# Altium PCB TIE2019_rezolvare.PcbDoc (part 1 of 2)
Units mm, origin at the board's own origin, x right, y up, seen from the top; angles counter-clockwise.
Board outline 267 x 129 mm, 8 copper layers (Signal 1, GND/Signal 2, GND 3, Signal 4, GND, Power/Signal 6, GND 7, Signal 8), stack 1.597 mm thick; 97 components, 82 nets, 657 pads, 352 vias.
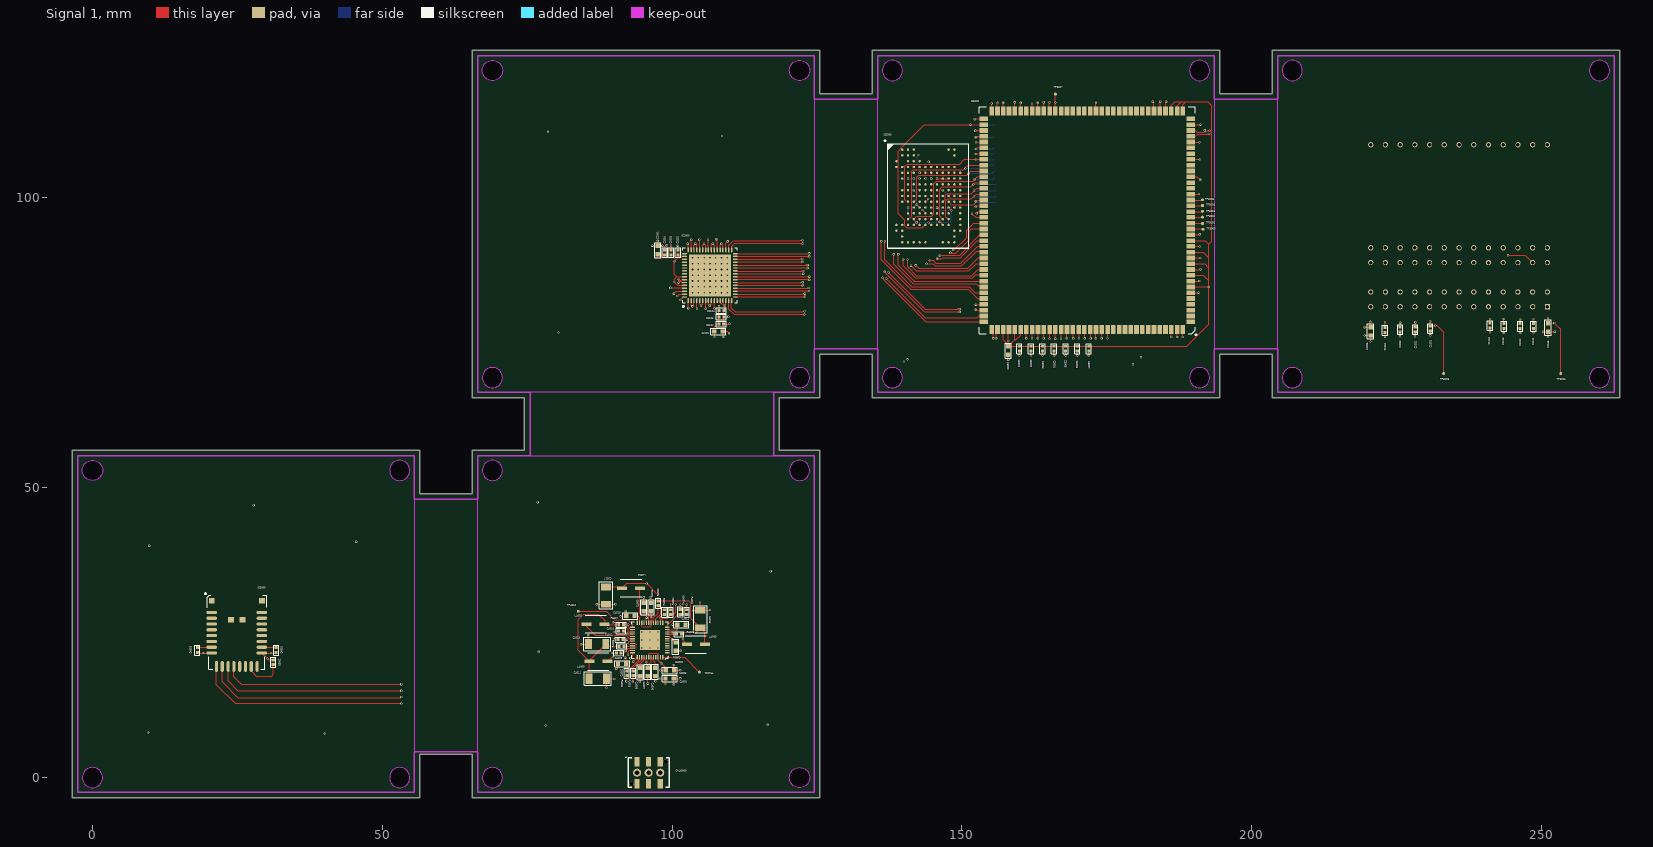
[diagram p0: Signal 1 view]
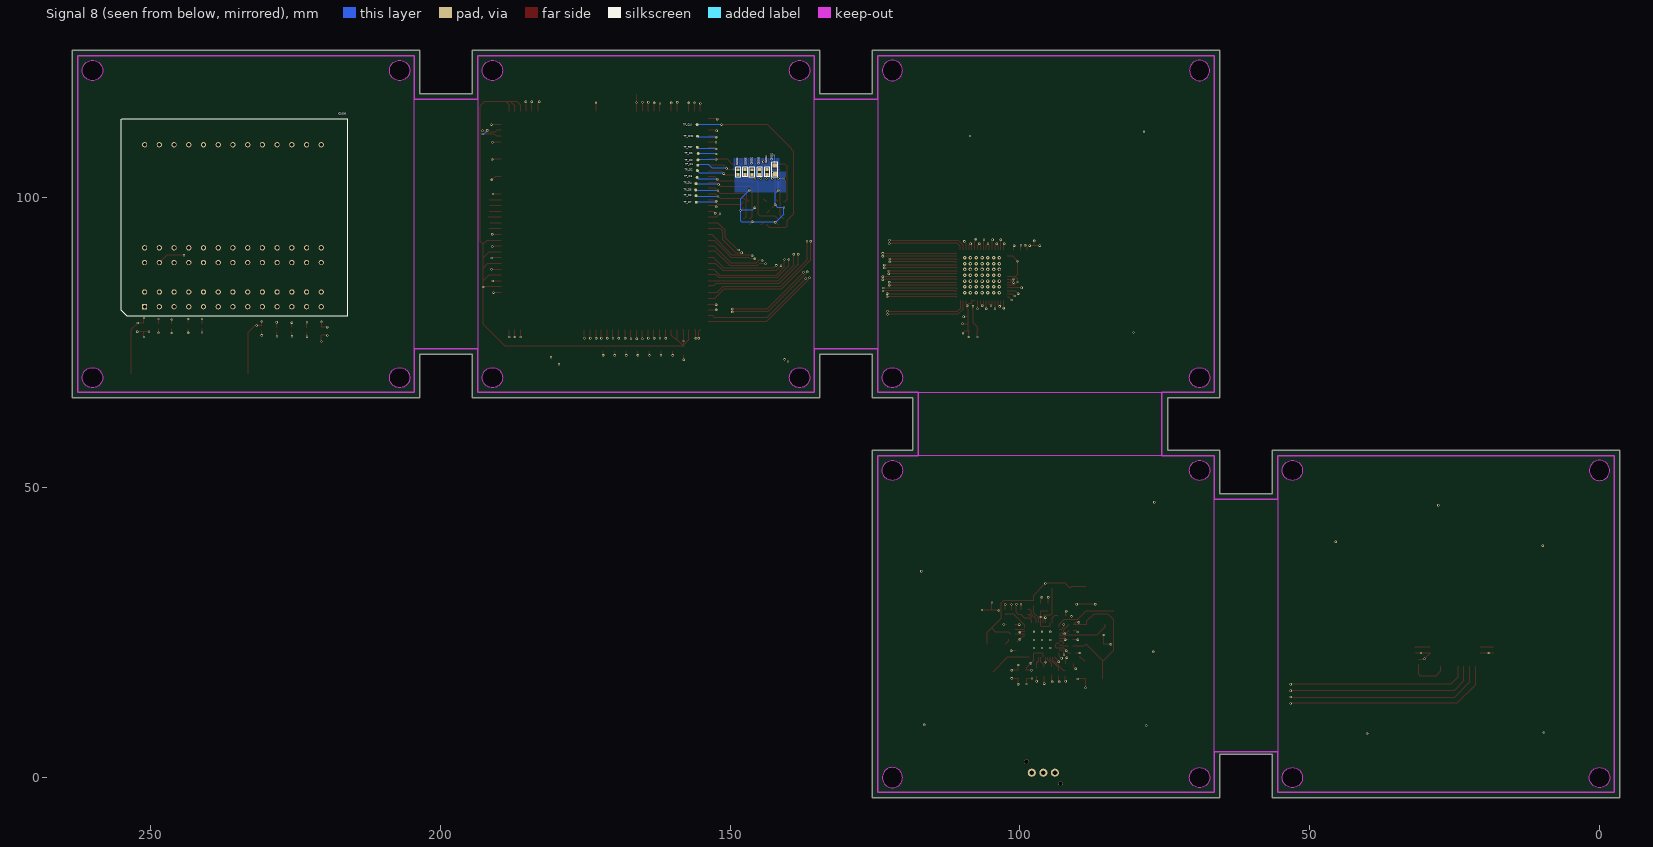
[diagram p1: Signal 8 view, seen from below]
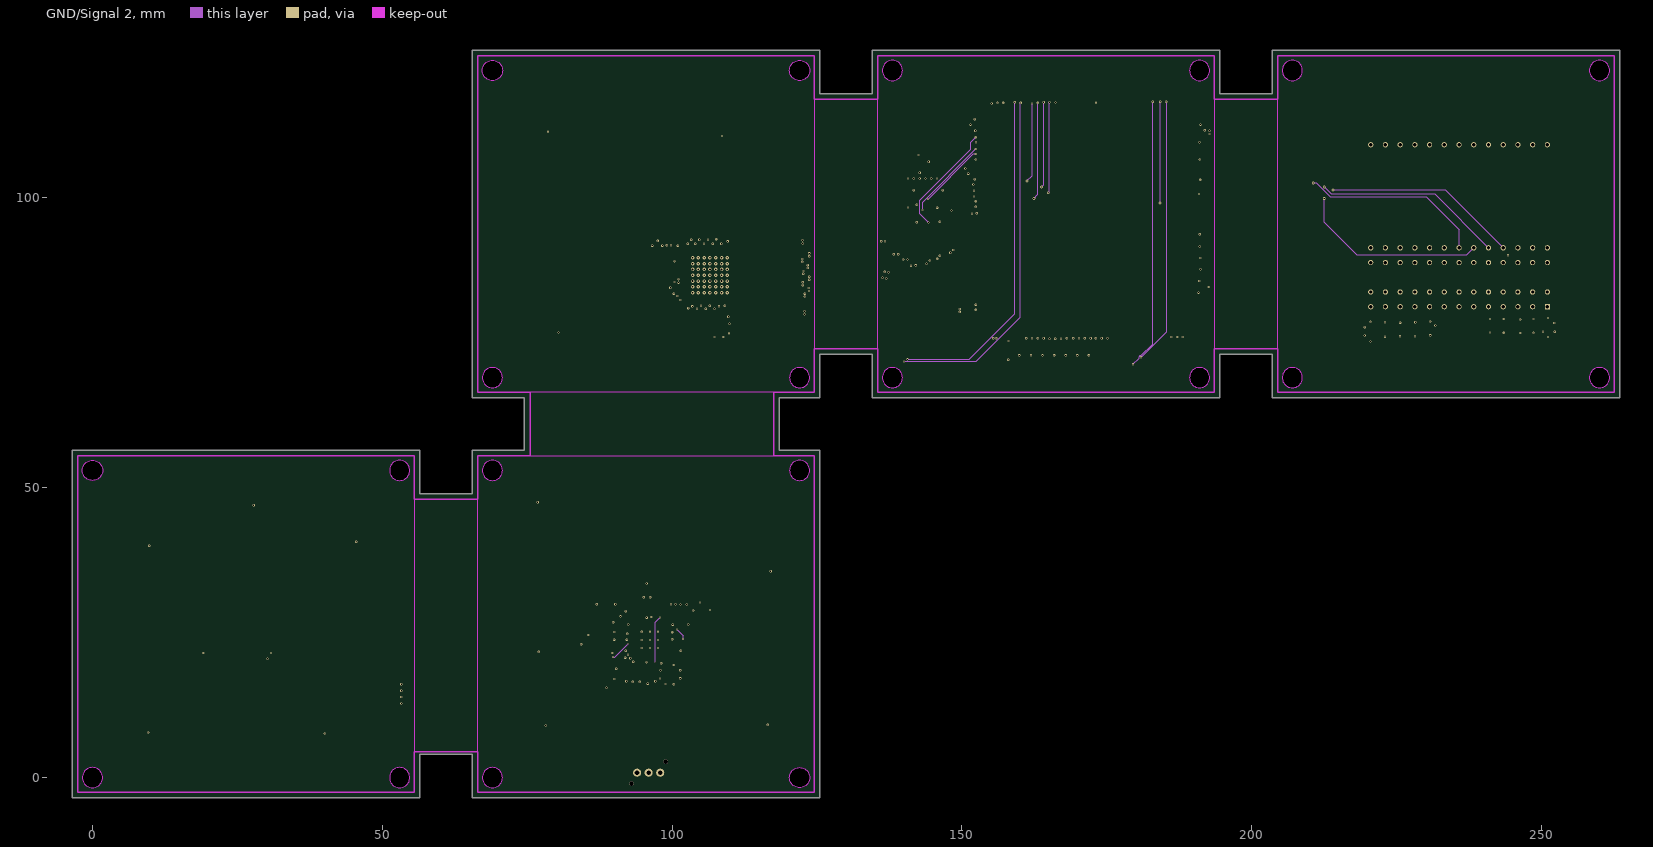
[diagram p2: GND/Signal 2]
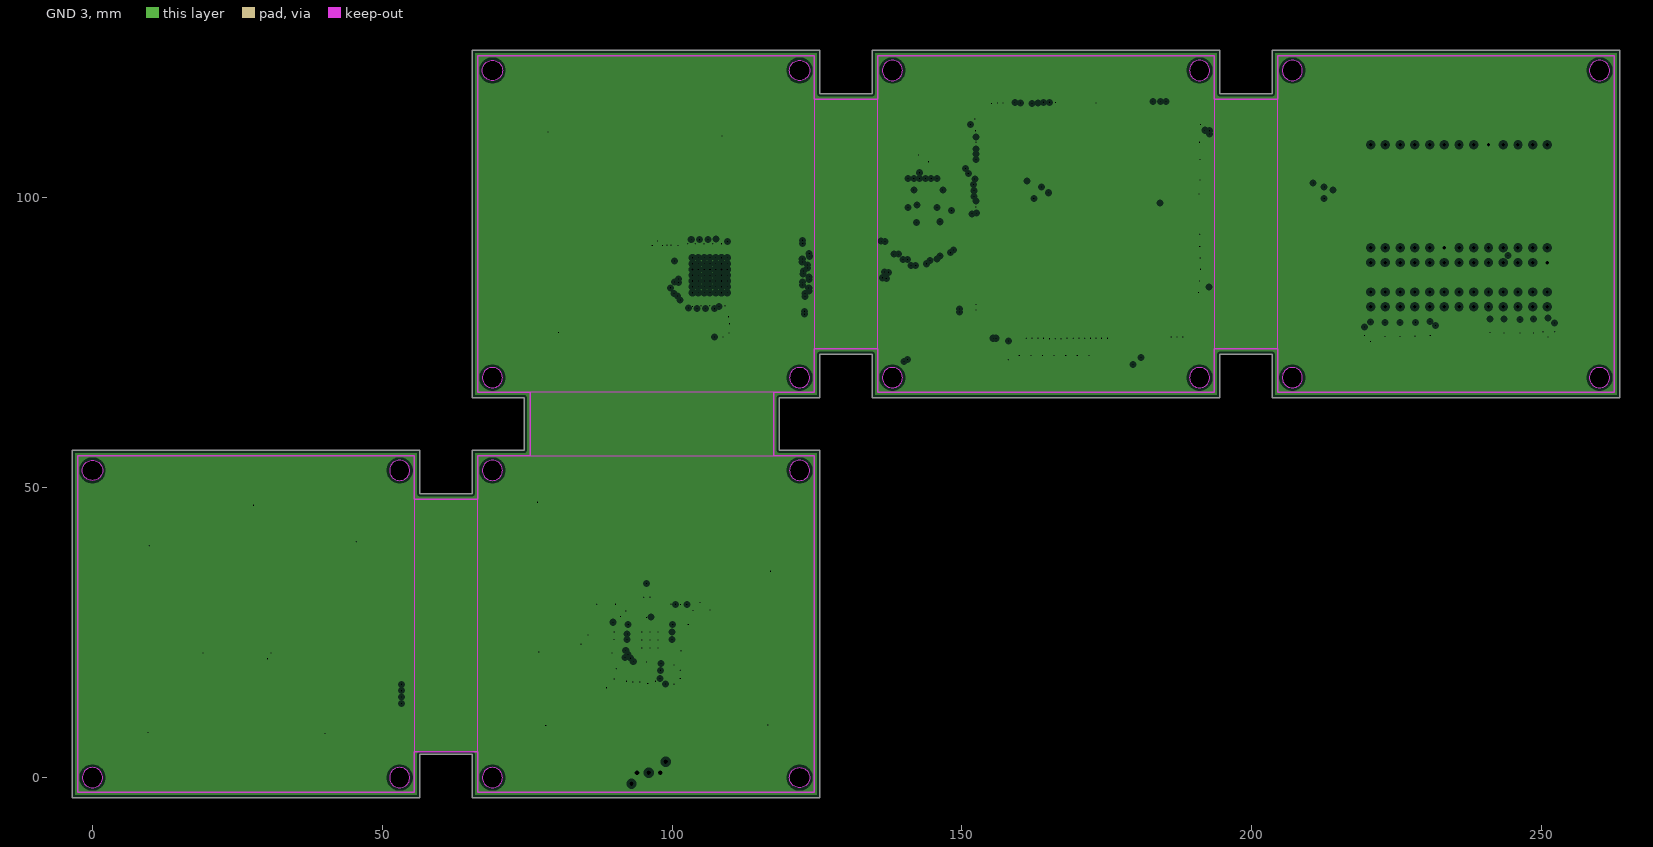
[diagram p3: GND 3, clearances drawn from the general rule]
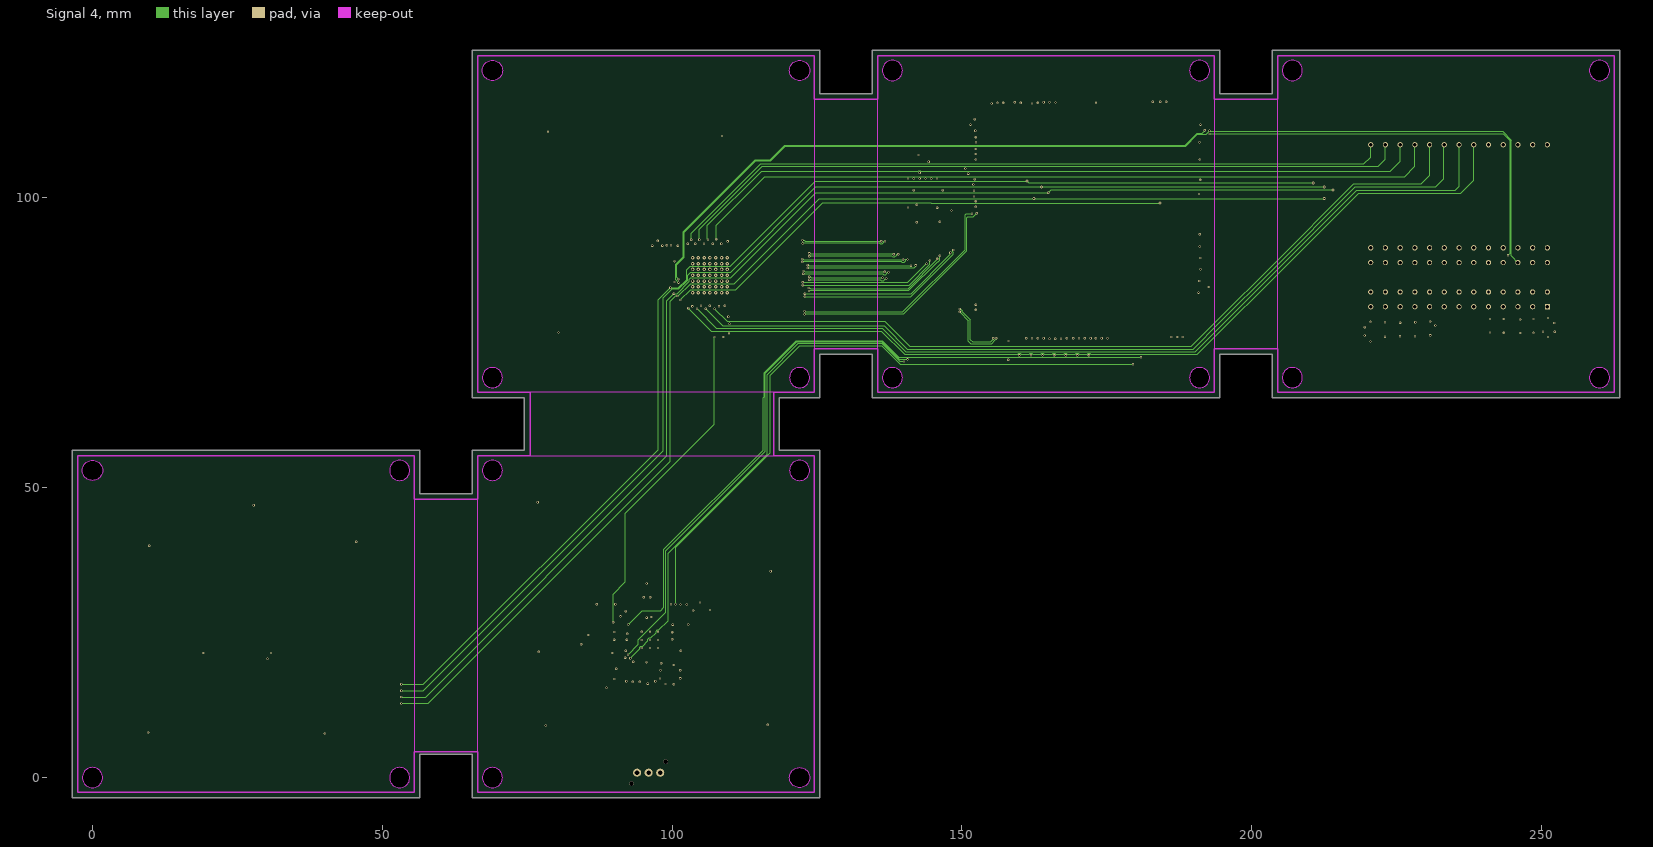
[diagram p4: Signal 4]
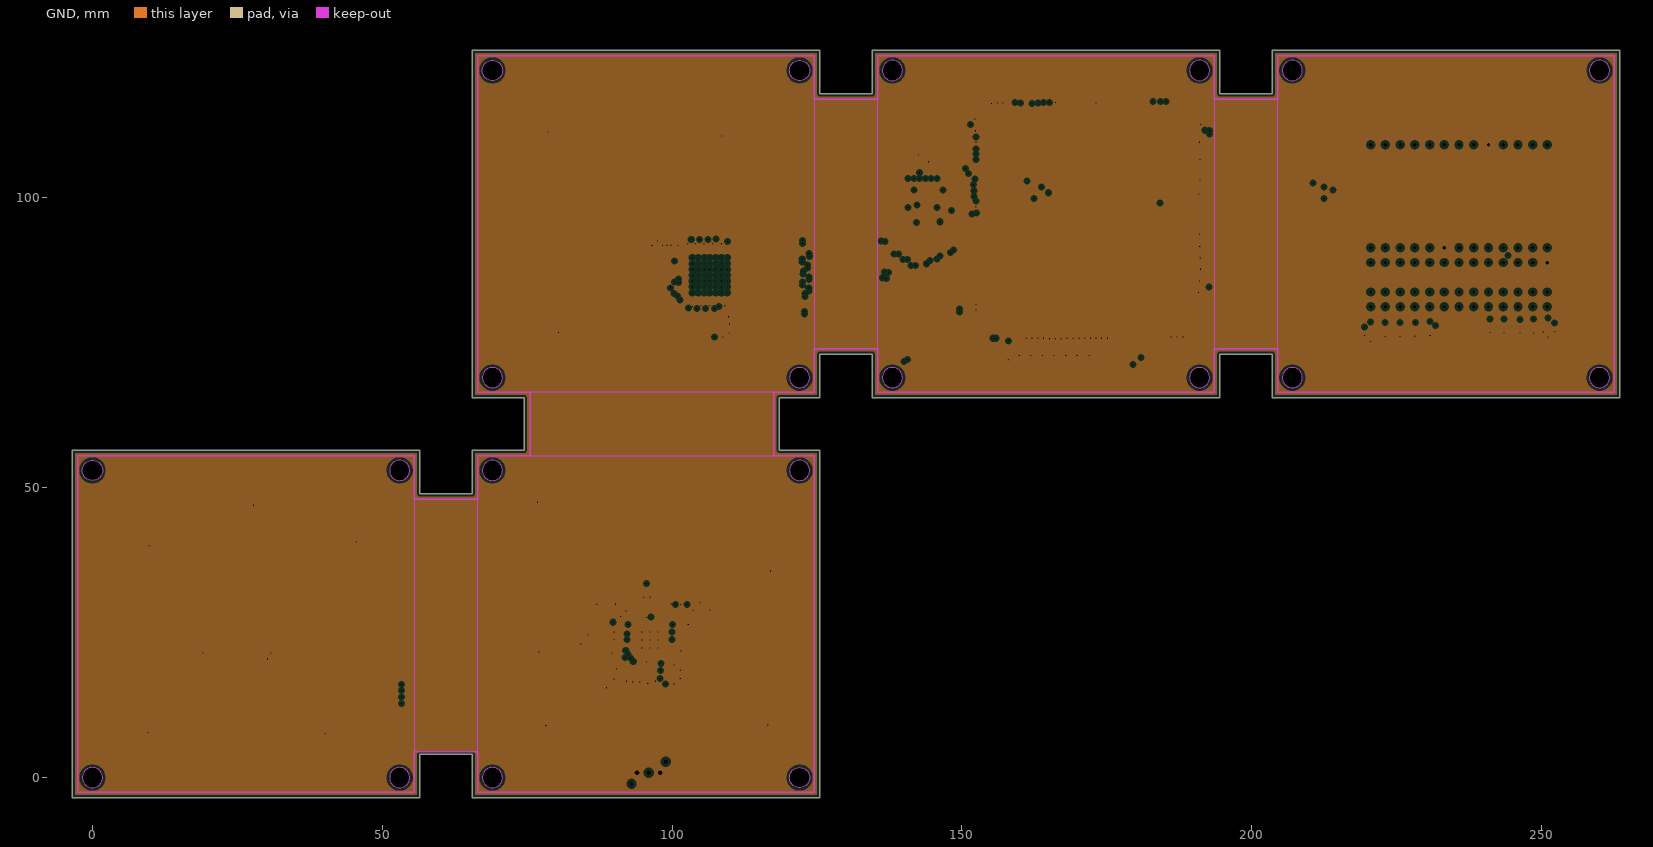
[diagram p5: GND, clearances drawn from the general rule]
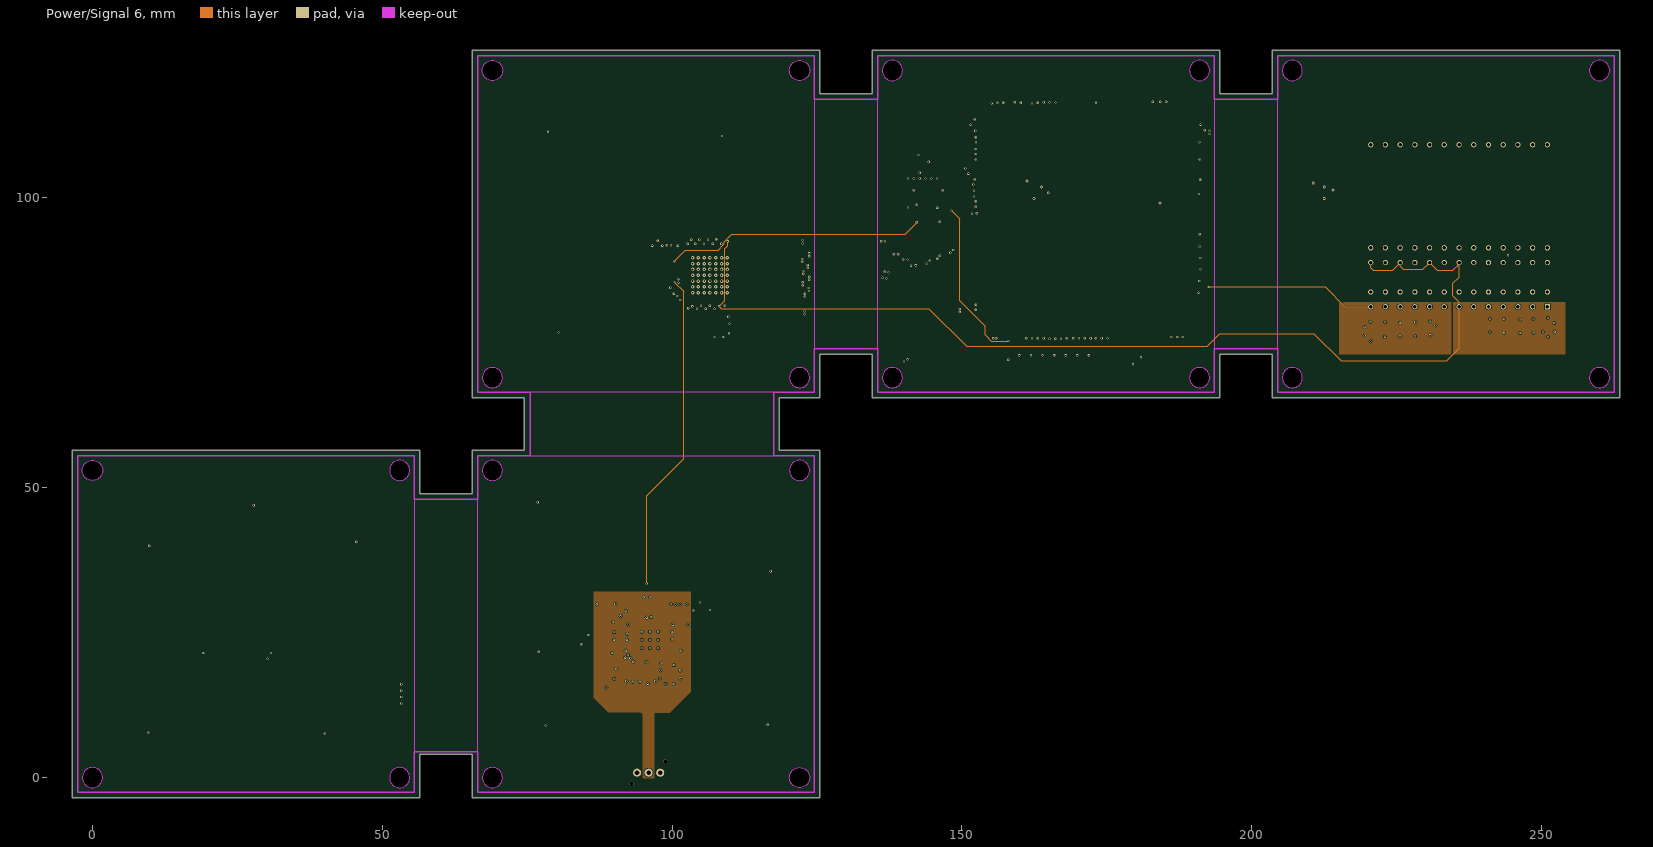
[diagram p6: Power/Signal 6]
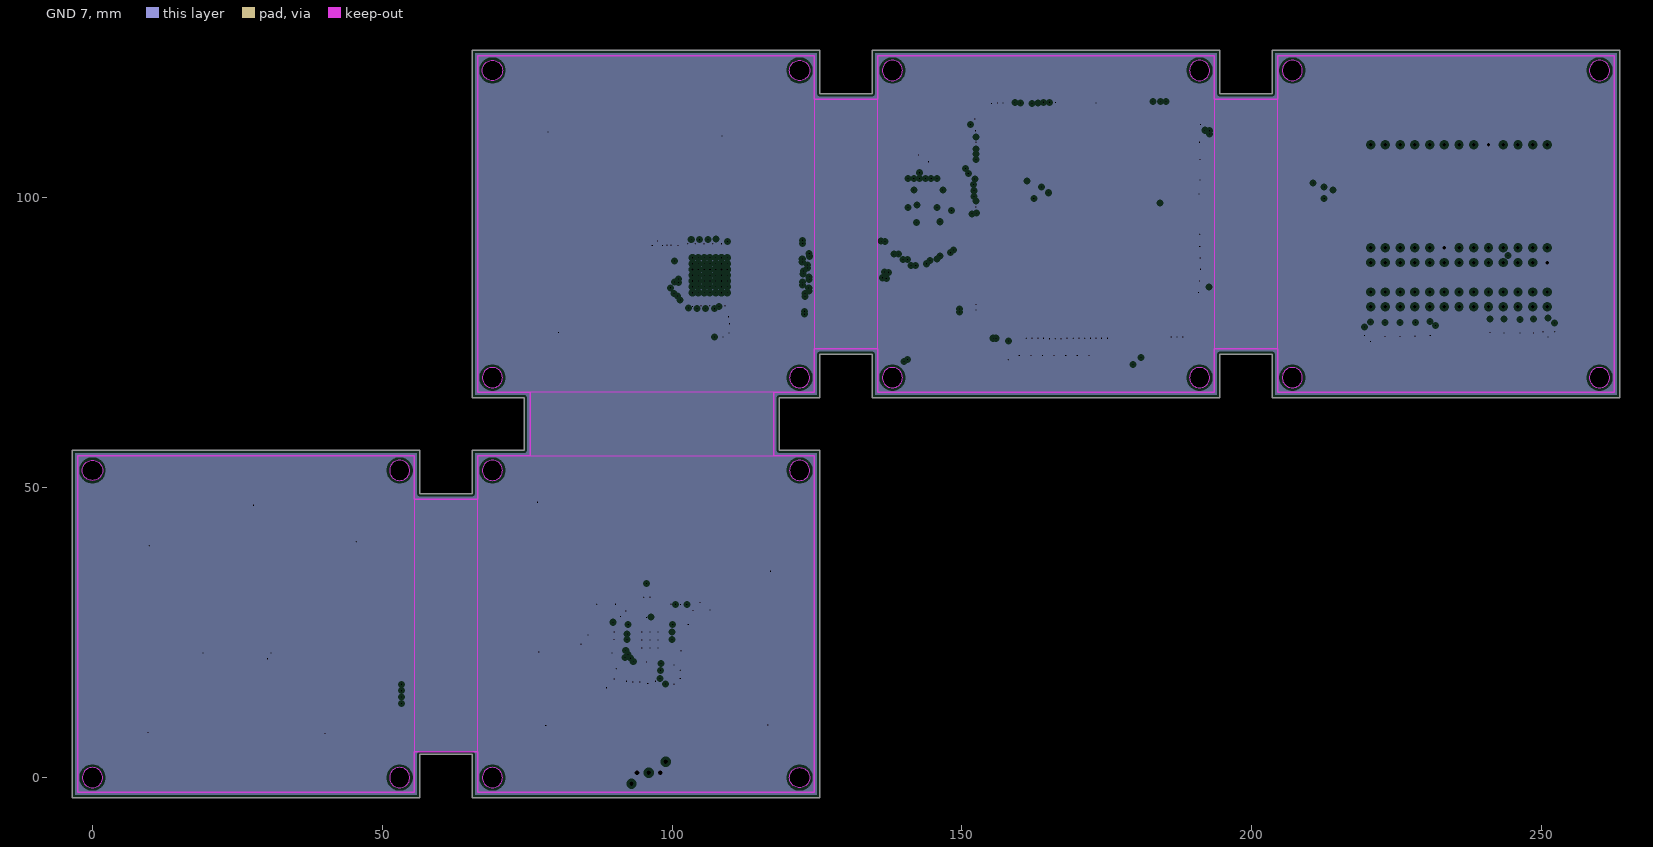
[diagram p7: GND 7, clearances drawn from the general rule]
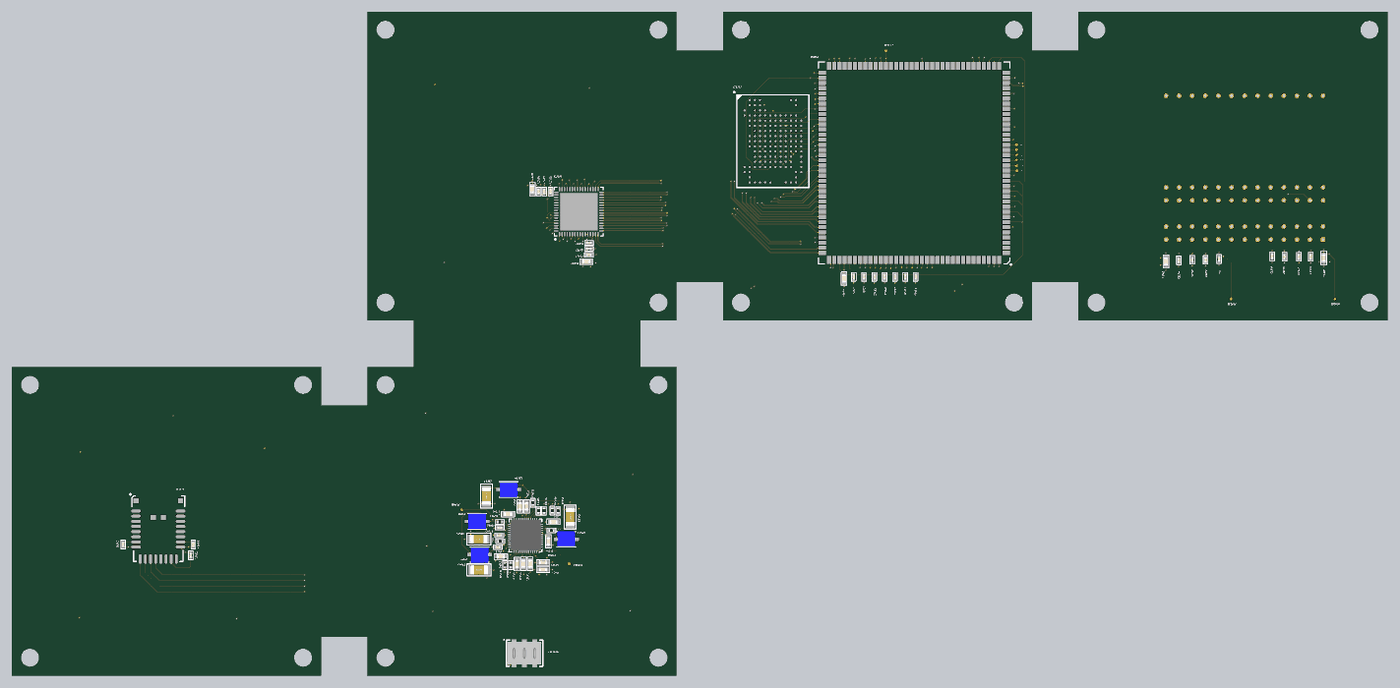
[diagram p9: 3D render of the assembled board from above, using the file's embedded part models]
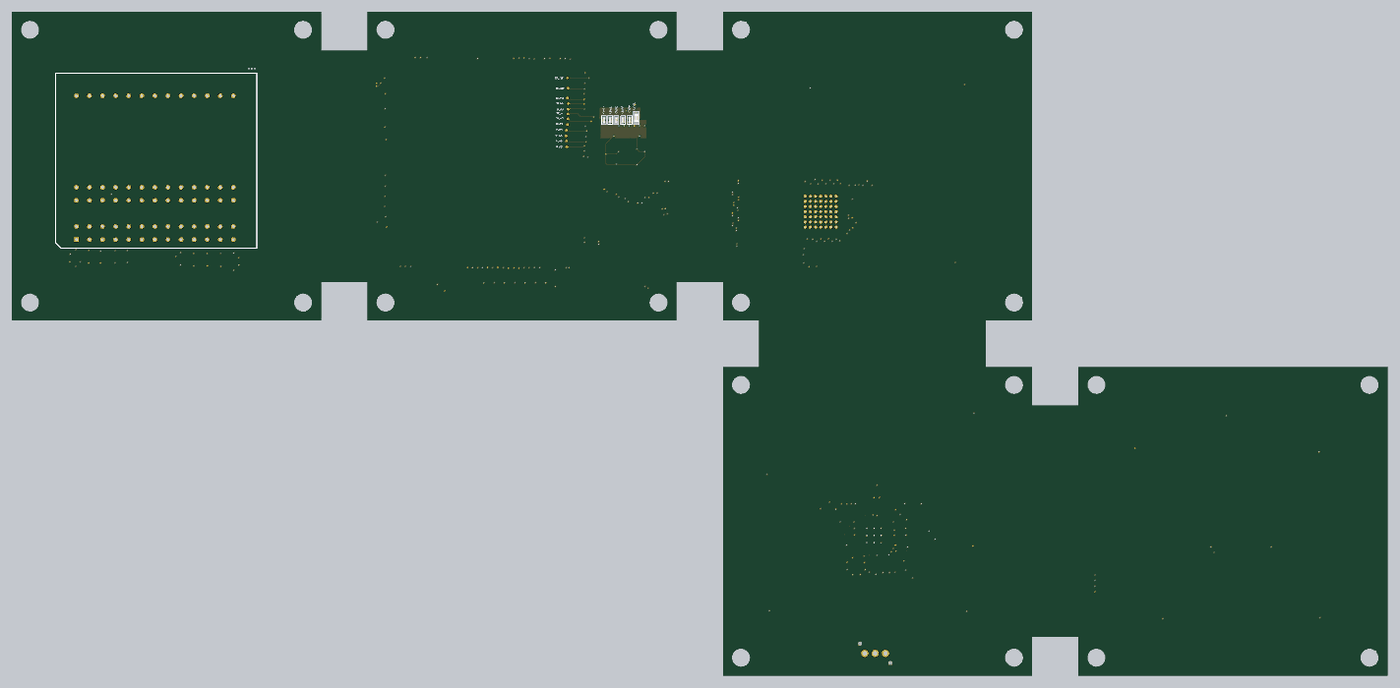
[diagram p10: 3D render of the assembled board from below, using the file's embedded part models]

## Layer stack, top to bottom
Top Solder: solder mask 0.05, FC-001, Dk 4
Top Solder: solder mask 0.02, Solder Resist, Dk 3.5
Signal 1: signal copper 0.43
Dielectric 2: prepreg 0.173, PP-006, Dk 4.1
GND/Signal 2: signal copper 0.043
Dielectric 4: prepreg 0.3, PP-006, Dk 4.1
GND 3: plane copper 0.018, net GND
Dielectric 5: prepreg 0.075, PP-006, Dk 4.1
Signal 4: signal copper 0.018
Dielectric 9: core 0.05, Composite dielectric, Dk 4.8
Dielectric 8: core 0.04, Core-009, Dk 4.5
Dielectric 1: core 0.05, Composite dielectric, Dk 4.8
GND: plane copper 0.018, net GND
Dielectric 6: prepreg 0.075, PP-006, Dk 4.1
Power/Signal 6: signal copper 0.018
Dielectric 7: prepreg 0.03, PP-006, Dk 4.1
GND 7: plane copper 0.043, net GND
Dielectric 3: prepreg 0.173, PP-006, Dk 4.1
Signal 8: signal copper 0.043
Flex Bottom Coverlay: solder mask 0.02, Solder Resist, Dk 3.5
Flex Bottom Coverlay: solder mask 0.05, FC-001, Dk 4

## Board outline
-3.5,-3.5 56.5,-3.5 56.5,4 65.5,4 65.5,-3.5 125.5,-3.5 125.5,56.5 118.5,56.5 118.5,65.5 125.5,65.5 125.5,73 134.5,73 134.5,65.5 194.5,65.5 194.5,73 203.5,73 203.5,65.5 263.5,65.5 263.5,125.5 203.5,125.5 203.5,118 194.5,118 194.5,125.5 134.5,125.5 134.5,118 125.5,118 125.5,125.5 65.5,125.5 65.5,65.5 74.5,65.5 74.5,56.5 65.5,56.5 65.5,49 56.5,49 56.5,56.5 -3.5,56.5
cut-out: 258.25,122 ccw(c260,122) 260,120.25 ccw(c260,122) 261.75,122 ccw(c260,122) 260,123.75 ccw(c260,122)
cut-out: 207,120.25 ccw(c207,122) 208.75,122 ccw(c207,122) 207,123.75 ccw(c207,122) 205.25,122 ccw(c207,122)
cut-out: 191,120.25 ccw(c191,122) 192.75,122 ccw(c191,122) 191,123.75 ccw(c191,122) 189.25,122 ccw(c191,122)
cut-out: 136.25,122 ccw(c138,122) 138,120.25 ccw(c138,122) 139.75,122 ccw(c138,122) 138,123.75 ccw(c138,122)
cut-out: 260,67.25 ccw(c260,69) 261.75,69 ccw(c260,69) 260,70.75 ccw(c260,69) 258.25,69 ccw(c260,69)
cut-out: 191,67.25 ccw(c191,69) 192.75,69 ccw(c191,69) 191,70.75 ccw(c191,69) 189.25,69 ccw(c191,69)
cut-out: 205.25,69 ccw(c207,69) 207,67.25 ccw(c207,69) 208.75,69 ccw(c207,69) 207,70.75 ccw(c207,69)
cut-out: 138,67.25 ccw(c138,69) 139.75,69 ccw(c138,69) 138,70.75 ccw(c138,69) 136.25,69 ccw(c138,69)
cut-out: 120.25,122 cw(c122,122) 122,123.75 cw(c122,122) 123.75,122 cw(c122,122) 122,120.25 cw(c122,122)
cut-out: 120.25,69 ccw(c122,69) 122,67.25 ccw(c122,69) 123.75,69 ccw(c122,69) 122,70.75 ccw(c122,69)
cut-out: 120.25,53 ccw(c122,53) 122,51.25 ccw(c122,53) 123.75,53 ccw(c122,53) 122,54.75 ccw(c122,53)
cut-out: 67.25,122 cw(c69,122) 69,123.75 cw(c69,122) 70.75,122 cw(c69,122) 69,120.25 cw(c69,122)
cut-out: 67.25,69 ccw(c69,69) 69,67.25 ccw(c69,69) 70.75,69 ccw(c69,69) 69,70.75 ccw(c69,69)
cut-out: 67.25,53 ccw(c69,53) 69,51.25 ccw(c69,53) 70.75,53 ccw(c69,53) 69,54.75 ccw(c69,53)
cut-out: 120.25,0 cw(c122,0) 122,1.75 cw(c122,0) 123.75,0 cw(c122,0) 122,-1.75 cw(c122,0)
cut-out: 67.25,0 ccw(c69,0) 69,-1.75 ccw(c69,0) 70.75,0 ccw(c69,0) 69,1.75 ccw(c69,0)
cut-out: 51.25,53 ccw(c53,53) 53,51.25 ccw(c53,53) 54.75,53 ccw(c53,53) 53,54.75 ccw(c53,53)
cut-out: 0,51.25 cw(c0,53) -1.75,53 cw(c0,53) 0,54.75 cw(c0,53) 1.75,53 cw(c0,53)
cut-out: 53,-1.75 ccw(c53,0) 54.75,0 ccw(c53,0) 53,1.75 ccw(c53,0) 51.25,0 ccw(c53,0)
cut-out: -1.75,0 ccw(c0,0) 0,-1.75 ccw(c0,0) 1.75,0 ccw(c0,0) 0,1.75 ccw(c0,0)
board region "RIGID A": 56.5,-3.5 -3.5,-3.5 -3.5,56.5 56.5,56.5
board region "Layer Stack Region 1": 65.5,4 56.5,4 56.5,49 65.5,49
board region "RIGID B": 125.5,56.5 125.5,-3.5 65.5,-3.5 65.5,49 65.5,56.5
board region "RIGID C": 125.5,73 125.5,65.5 118.5,65.5 65.5,65.5 65.5,125.5 125.5,125.5
board region "Layer Stack Region 2": 118.5,65.5 118.5,56.5 74.5,56.5 74.5,65.5
board region "Layer Stack Region 3": 134.5,73 125.5,73 125.5,118 134.5,118
board region "RIGID D": 194.5,73 194.5,65.5 134.5,65.5 134.5,118 134.5,125.5 194.5,125.5
board region "Layer Stack Region 4": 203.5,73 194.5,73 194.5,118 203.5,118
board region "RIGID E": 203.5,118 203.5,125.5 263.5,125.5 263.5,65.5 203.5,65.5

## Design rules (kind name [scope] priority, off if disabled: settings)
Clearance Clearance_1 [All] p1: gap=0.1 ignorepadtopadclearanceinfootprint=FALSE
Clearance [InNetClass('eMMC_Bus')] p2: gap=0.21 ignorepadtopadclearanceinfootprint=FALSE
DiffPairsRouting DiffPairsRouting_LVDS_DIFF [InDifferentialPairClass('LVDS_DIFF')] p1: maxlimit=0.23 minlimit=0.23 mostfreqgap=0.23 toplayer_minwidth=0.2 toplayer_maxwidth=0.2 toplayer_prefwidth=0.2 midlayer1_minwidth=0.09 midlayer1_maxwidth=0.09 midlayer1_prefwidth=0.09 midlayer2_minwidth=0.09 midlayer2_maxwidth=0.09 midlayer2_prefwidth=0.09 midlayer3_minwidth=0.09 midlayer3_maxwidth=0.09 midlayer3_prefwidth=0.09 bottomlayer_minwidth=0.2 bottomlayer_maxwidth=0.2 bottomlayer_prefwidth=0.2 substack1={2D9F6985-649F-40C4-A361-7E10F32C00A7} toplayer_{2d9f6985-649f-40c4-a361-7e10f32c00a7}_mingap=0.2 toplayer_{2d9f6985-649f-40c4-a361-7e10f32c00a7}_maxgap=0.2 toplayer_{2d9f6985-649f-40c4-a361-7e10f32c00a7}_prefgap=0.2 toplayer_{2d9f6985-649f-40c4-a361-7e10f32c00a7}_minwidth=0.09 toplayer_{2d9f6985-649f-40c4-a361-7e10f32c00a7}_maxwidth=0.09 toplayer_{2d9f6985-649f-40c4-a361-7e10f32c00a7}_prefwidth=0.09 midlayer1_{2d9f6985-649f-40c4-a361-7e10f32c00a7}_mingap=0.2 midlayer1_{2d9f6985-649f-40c4-a361-7e10f32c00a7}_maxgap=0.2 midlayer1_{2d9f6985-649f-40c4-a361-7e10f32c00a7}_prefgap=0.2 midlayer1_{2d9f6985-649f-40c4-a361-7e10f32c00a7}_minwidth=0.09 midlayer1_{2d9f6985-649f-40c4-a361-7e10f32c00a7}_maxwidth=0.09 midlayer1_{2d9f6985-649f-40c4-a361-7e10f32c00a7}_prefwidth=0.09 midlayer2_{2d9f6985-649f-40c4-a361-7e10f32c00a7}_minwidth=0.09 midlayer2_{2d9f6985-649f-40c4-a361-7e10f32c00a7}_maxwidth=0.09 midlayer2_{2d9f6985-649f-40c4-a361-7e10f32c00a7}_prefwidth=0.09 midlayer3_{2d9f6985-649f-40c4-a361-7e10f32c00a7}_minwidth=0.09 midlayer3_{2d9f6985-649f-40c4-a361-7e10f32c00a7}_maxwidth=0.09 midlayer3_{2d9f6985-649f-40c4-a361-7e10f32c00a7}_prefwidth=0.09 bottomlayer_{2d9f6985-649f-40c4-a361-7e10f32c00a7}_mingap=0.2 bottomlayer_{2d9f6985-649f-40c4-a361-7e10f32c00a7}_maxgap=0.2 bottomlayer_{2d9f6985-649f-40c4-a361-7e10f32c00a7}_prefgap=0.2 bottomlayer_{2d9f6985-649f-40c4-a361-7e10f32c00a7}_minwidth=0.09 bottomlayer_{2d9f6985-649f-40c4-a361-7e10f32c00a7}_maxwidth=0.09 bottomlayer_{2d9f6985-649f-40c4-a361-7e10f32c00a7}_prefwidth=0.09 filterlayerstackid={3405C773-BCB3-445C-810F-5A09EFCF737A} maxuncoupledlength=3
DiffPairsRouting DiffPairsRouting_DIFF_PAIRS [InDifferentialPairClass('DIFF_PAIRS')] p2: maxlimit=0.23 minlimit=0.23 mostfreqgap=0.23 toplayer_minwidth=0.2 toplayer_maxwidth=0.2 toplayer_prefwidth=0.2 midlayer1_minwidth=0.09 midlayer1_maxwidth=0.09 midlayer1_prefwidth=0.09 midlayer2_minwidth=0.09 midlayer2_maxwidth=0.09 midlayer2_prefwidth=0.09 midlayer3_minwidth=0.09 midlayer3_maxwidth=0.09 midlayer3_prefwidth=0.09 bottomlayer_minwidth=0.2 bottomlayer_maxwidth=0.2 bottomlayer_prefwidth=0.2 substack1={2D9F6985-649F-40C4-A361-7E10F32C00A7} toplayer_{2d9f6985-649f-40c4-a361-7e10f32c00a7}_mingap=0.2 toplayer_{2d9f6985-649f-40c4-a361-7e10f32c00a7}_maxgap=0.2 toplayer_{2d9f6985-649f-40c4-a361-7e10f32c00a7}_prefgap=0.2 toplayer_{2d9f6985-649f-40c4-a361-7e10f32c00a7}_minwidth=0.09 toplayer_{2d9f6985-649f-40c4-a361-7e10f32c00a7}_maxwidth=0.09 toplayer_{2d9f6985-649f-40c4-a361-7e10f32c00a7}_prefwidth=0.09 midlayer1_{2d9f6985-649f-40c4-a361-7e10f32c00a7}_mingap=0.2 midlayer1_{2d9f6985-649f-40c4-a361-7e10f32c00a7}_maxgap=0.2 midlayer1_{2d9f6985-649f-40c4-a361-7e10f32c00a7}_prefgap=0.2 midlayer1_{2d9f6985-649f-40c4-a361-7e10f32c00a7}_minwidth=0.09 midlayer1_{2d9f6985-649f-40c4-a361-7e10f32c00a7}_maxwidth=0.09 midlayer1_{2d9f6985-649f-40c4-a361-7e10f32c00a7}_prefwidth=0.09 midlayer2_{2d9f6985-649f-40c4-a361-7e10f32c00a7}_minwidth=0.09 midlayer2_{2d9f6985-649f-40c4-a361-7e10f32c00a7}_maxwidth=0.09 midlayer2_{2d9f6985-649f-40c4-a361-7e10f32c00a7}_prefwidth=0.09 midlayer3_{2d9f6985-649f-40c4-a361-7e10f32c00a7}_minwidth=0.09 midlayer3_{2d9f6985-649f-40c4-a361-7e10f32c00a7}_maxwidth=0.09 midlayer3_{2d9f6985-649f-40c4-a361-7e10f32c00a7}_prefwidth=0.09 bottomlayer_{2d9f6985-649f-40c4-a361-7e10f32c00a7}_mingap=0.2 bottomlayer_{2d9f6985-649f-40c4-a361-7e10f32c00a7}_maxgap=0.2 bottomlayer_{2d9f6985-649f-40c4-a361-7e10f32c00a7}_prefgap=0.2 bottomlayer_{2d9f6985-649f-40c4-a361-7e10f32c00a7}_minwidth=0.09 bottomlayer_{2d9f6985-649f-40c4-a361-7e10f32c00a7}_maxwidth=0.09 bottomlayer_{2d9f6985-649f-40c4-a361-7e10f32c00a7}_prefwidth=0.09 filterlayerstackid={3405C773-BCB3-445C-810F-5A09EFCF737A} maxuncoupledlength=3
Height [All] p1: minheight=0 maxheight=30 prefheight=12.7
HoleToHoleClearance [All] p1: gap=0.1 allowstackedmicrovias=TRUE
MinimumSolderMaskSliver [All] p1: minsoldermaskwidth=0.1
PlaneClearance [All] p1: clearance=0.508
PlaneConnect [All] p1: planeconnectstyle=Relief reliefexpansion=0.2 reliefentries=2 reliefconductorwidth=0.1 reliefairgap=0.1
PolygonConnect [All] p1: connectstyle=Relief reliefconductorwidth=0.1 reliefentries=2 polygonreliefangle="90 Angle" airgapwidth=0.1
RoutingVias RoutingVias_Buried [IsVia AND (StartLayer = 'GND/Signal 2') AND (StopLayer = 'GND 7')] p1: holewidth=0.2 width=0.5 viastyle="Through Hole" minholewidth=0.2 minwidth=0.5 maxholewidth=0.2 maxwidth=0.5
RoutingVias RoutingVias_BLIND7_8 [IsVia AND (StartLayer = 'GND 7') AND (StopLayer = 'Signal 8')] p2: holewidth=0.125 width=0.325 viastyle="Through Hole" minholewidth=0.125 minwidth=0.325 maxholewidth=0.125 maxwidth=0.325
RoutingVias RoutingVias_BLIND1_2 [IsVia AND (StartLayer = 'Signal 1') AND (StopLayer = 'GND/Signal 2')] p3: holewidth=0.125 width=0.325 viastyle="Through Hole" minholewidth=0.125 minwidth=0.325 maxholewidth=0.125 maxwidth=0.325
RoutingVias [All] p4: holewidth=0.2 width=0.4 viastyle="Through Hole" minholewidth=0.2 minwidth=0.4 maxholewidth=0.2 maxwidth=0.4
SilkToSilkClearance [All] p1: silktosilkclearance=0.1
SilkToSolderMaskClearance [IsPad] p1: minsilkscreentomaskgap=0.1 clearancetoexposedcopper=TRUE
SolderMaskExpansion [All] p1: expansion=0.102 istentingtop=FALSE
SupplyNets "Schematic Supply Nets_6" [InNet('+V_LDO_RF_3V3')] p1: voltage=0.000
SupplyNets "Schematic Supply Nets_5" [InNet('GND')] p2: voltage=0.000
SupplyNets "Schematic Supply Nets_3" [InNet('+V_SMPS_1V8')] p3: voltage=0.000
SupplyNets "Schematic Supply Nets_2" [InNet('+V_IN')] p4: voltage=0.000
SupplyNets "Schematic Supply Nets_1" [InNet('+V_SMPS_3V3')] p5: voltage=0.000
Width [All] p1: maxlimit=0.1 minlimit=0.07 preferedwidth=0.07 substack1={2D9F6985-649F-40C4-A361-7E10F32C00A7}
22 further rules are at their usual default settings.

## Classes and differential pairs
component class TIE_2019_rezolvare_page_2: C1001 C1002 C1003 C1004 C1005 C1101 C1102 C1103 C1104 C1105 C2001 C2002 C2003 C2004 C2101 C2102 C2103 C2104 C3000 C3001 C3002 C3003 C3004 C3005 C3006 C3007 C5001 C5002 C5003 C5004 C5005 C5006 C6001 C6002 C6003 IC1000 IC2000 IC3000 IC5000 IC6000 TP3000 TP3001 TP3002 TP3003 TP3004 TP3005 TP3006 TP3007 TP3008 TP_CLK TP_CMD TP_D0 TP_D1 TP_D2 TP_D3 TP_D4 TP_D5 TP_D6 TP_D7 TP_DS TP_RST
component class TIE_2019_rezolvare_page_1: C4001 C4002 C4003 C4004 C4005 C4006 C4007 C4008 C4009 C4010 C4011 C4012 C4013 C4014 C4015 C4016 C4017 C4019 CN40000 IC4000 L4000 L4002 L4003 L4004 R4001 R4002 R4003 R4004 R4005 R4006 R4007 R4008 R4009 TH4000 TP4010 TP4011
differential pair LVDS_D7: +LVDS_D7_P -LVDS_D7_N
differential pair LVDS_D6: +LVDS_D6_P -LVDS_D6_N
differential pair LVDS_D5: +LVDS_D5_P -LVDS_D5_N
differential pair LVDS_D4: +LVDS_D4_P -LVDS_D4_N
differential pair LVDS_D3: +LVDS_D3_P -LVDS_D3_N
differential pair LVDS_D2: +LVDS_D2_P -LVDS_D2_N
differential pair LVDS_D1: +LVDS_D1_P -LVDS_D1_N
differential pair LVDS_D0: +LVDS_D0_P -LVDS_D0_N
differential pair FRAME_CLK: +FRAME_CLK_P -FRAME_CLK_N
differential pair BIT_CLK: +BIT_CLK_P -BIT_CLK_N
differential pair ADC_CLK: +ADC_CLK_P -ADC_CLK_N

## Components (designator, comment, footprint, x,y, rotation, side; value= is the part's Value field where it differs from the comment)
C1001 "100nF" CAP0402 230.8,77.48 r90 top
C1002 "100nF" CAP0402 228.2,77.3 r90 top
C1003 "100nF" CAP0402 225.6,77.3 r90 top
C1004 "100nF" CAP0402 223,77.2 r90 top
C1005 "10uF" CAP0603 220.5,77 r90 top
C1101 "100nF" CAP0402 248.6,77.9 r90 top
C1102 "100nF" CAP0402 246.3,77.9 r90 top
C1103 "100nF" CAP0402 243.5,77.9 r90 top
C1104 "100nF" CAP0402 241.1,78 r90 top
C1105 "10uF" CAP0603 251.118,77.655 r90 top
C2001 "10uF" CAP0603 97.525,91.02 r270 top
C2002 "100nF" CAP0402 101.025,90.585 r270 top
C2003 "100nF" CAP0402 99.825,90.585 r270 top
C2004 "100nF" CAP0402 98.725,90.585 r270 top
C2101 "10uF" CAP0603 108,76.975 r180 top
C2102 "100nF" CAP0402 108.481,78.257 r180 top
C2103 "100nF" CAP0402 108.5,79.475 r180 top
C2104 "100nF" CAP0402 108.5,80.6 r180 top
C3000 "10uF" CAP0603 158,73.68 r270 top
C3001 "100nF" CAP0402 159.9,74 r270 top
C3002 "100nF" CAP0402 161.9,74 r270 top
C3003 "10nF" CAP0402 163.9,74 r270 top
C3004 "100nF" CAP0402 165.9,74 r270 top
C3005 "100nF" CAP0402 167.9,74 r270 top
C3006 "100nF" CAP0402 169.9,74 r270 top
C3007 "100nF" CAP0402 171.9,74 r270 top
C4001 "10uF" CAP0603 99.58,17.1 r180 top
C4002 "10uF" CAP0603 91.395,19.65 r0 top
C4003 "2.2uF" CAP0603 95.1,29.4 r270 top
C4004 "2.2uF" CAP0603 100.6,22.6 r270 top
C4005 "2.2uF" CAP0603 99.6,18.5 r0 top
C4006 "2.2uF" CAP0603 97.075,18.25 r90 top
C4007 "2.2uF" CAP0603 95.775,18.25 r90 top
C4008 "2.2uF" CAP0603 94.5,18.2 r90 top
C4009 "100nF" CAP0402 90.8,21.5 r0 top
C4010 "4.7uF" CAP0402 91.18,25.3 r180 top
C4011 "47uF" CAP1206 87.175,17.05 r180 top
C4012 "4.7uF" CAP0402 91.08,23.8 r180 top
C4013 "47uF" CAP1206 87.075,23.05 r0 top
C4014 "4.7uF" CAP0603 101.6,26.4 r0 top
C4015 "47uF" CAP1206 104.875,27.35 r270 top
C4016 "4.7uF" CAP0603 96.4,29.4 r90 top
C4017 "47uF" CAP1206 88.6,31.4 r90 top
C4019 "2.2uF" CAP0603 92.78,27.9 r0 top
C5001 "10uF" CAP0603 142.3,104.87 r90 bottom
C5002 "100nF" CAP0402 146.2,104.45 r90 bottom
C5003 "100nF" CAP0402 148.6,104.45 r90 bottom
C5004 "100nF" CAP0402 143.6,104.47 r270 bottom
C5005 "100nF" CAP0402 144.9,104.47 r270 bottom
C5006 "100nF" CAP0402 147.4,104.47 r270 bottom
C6001 "100nF" CAP0402 31.7,22 r90 top
C6002 "100nF" CAP0402 31.2,19.9 r270 top
C6003 "100nF" CAP0402 18.1,22 r90 top
CN40000 "Connector 1x3" CONN1X03 95.95,0.85 r0 top
IC1000 "PGA65" PGAx13 251,81.24 r180 bottom
IC2000 "ADC219" QFN64 106.524,86.665 r90 top
IC3000 "IMX6-CPU" IMX6-SoM 171.625,96.15 r90 top
IC4000 "PMIC219" 48-QFN 96.175,23.75 r180 top
IC5000 "eMMC219" BGA100 144.2,100.35 r0 top
IC6000 "TRX219" A1101R09C00GM 24.9,25 r0 top
L4000 "1uH/4.2A" L_1212AB 87.275,20.05 r180 top
L4002 "1uH/4.2A" L_1212AB 86.8,26.5 r0 top
L4003 "1uH/4.2A" L_1212AB 104.1,23 r0 top
L4004 "1uH/4.2A" L_1212AB 92.9,32.7 r180 top
R4001 "4.7k" RES0402 102.525,28.55 r90 top
R4002 "0R" RES0402 92.2,17.99 r90 top
R4003 "0R" RES0402 93.3,18 r90 top
R4004 "49.9R" RES0402 99.775,28.55 r270 top
R4005 "10k" RES0402 98.675,28.55 r270 top
R4006 "0R" RES0402 91.285,22.65 r180 top
R4007 "0R" RES0402 91.205,26.385 r180 top
R4008 "0R" RES0402 101.195,24.75 r0 top
R4009 "0R" RES0402 97.6,30.1 r90 top
TH4000 "10K" RES0402 101.4,28.59 r270 top
TP3000 "TestPoint" TestPoint_2019 191.6,94.6 r90 top
TP3001 "TestPoint" TestPoint_2019 191.5,95.6 r90 top
TP3002 "TestPoint" TestPoint_2019 191.5,96.7 r90 top
TP3003 "TestPoint" TestPoint_2019 191.5,97.7 r90 top
TP3004 "TestPoint" TestPoint_2019 191.5,98.7 r180 top
TP3005 "TestPoint" TestPoint_2019 191.5,99.7 r90 top
TP3006 "TestPoint" TestPoint_2019 253.3,69.7 r90 top
TP3007 "TestPoint" TestPoint_2019 166.127,117.927 r90 top
TP3008 "TestPoint" TestPoint_2019 233.1,69.7 r90 top
TP4010 "TestPoint" TestPoint_2019 83.8,28.7 r270 top
TP4011 "TestPoint" TestPoint_2019 104.7,18.2 r270 top
TP_CLK "TestPoint" TestPoint_2019 155.677,112.649 r180 bottom
TP_CMD "TestPoint" TestPoint_2019 155.6,110.642 r180 bottom
TP_D0 "TestPoint" TestPoint_2019 155.55,106.578 r180 bottom
TP_D1 "TestPoint" TestPoint_2019 155.575,105.639 r180 bottom
TP_D2 "TestPoint" TestPoint_2019 155.626,104.724 r180 bottom
TP_D3 "TestPoint" TestPoint_2019 155.677,103.556 r180 bottom
TP_D4 "TestPoint" TestPoint_2019 155.88,102.489 r180 bottom
TP_D5 "TestPoint" TestPoint_2019 155.931,101.397 r180 bottom
TP_D6 "TestPoint" TestPoint_2019 155.88,100.406 r180 bottom
TP_D7 "TestPoint" TestPoint_2019 155.829,99.263 r180 bottom
TP_DS "TestPoint" TestPoint_2019 155.499,107.671 r180 bottom
TP_RST "TestPoint" TestPoint_2019 155.651,108.737 r180 bottom

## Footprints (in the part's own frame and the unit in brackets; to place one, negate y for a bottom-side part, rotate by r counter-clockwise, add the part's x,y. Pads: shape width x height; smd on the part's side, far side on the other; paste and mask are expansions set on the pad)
48-QFN [mm] "6x6mm QFN Package"
  rect 0.8x0.2 smd mask+0.05: 1(-3,2.2) 2(-3,1.8) 3(-3,1.4) 4(-3,1) 5(-3,0.6) 6(-3,0.2) 7(-3,-0.2) 8(-3,-0.6) 9(-3,-1) 10(-3,-1.4) 11(-3,-1.8) 12(-3,-2.2) 25(3,-2.2) 26(3,-1.8) 27(3,-1.4) 28(3,-1) 29(3,-0.6) 30(3,-0.2) 31(3,0.2) 32(3,0.6) 33(3,1) 34(3,1.4) 35(3,1.8) 36(3,2.2)
  rect 0.2x0.8 smd mask+0.05: 13(-2.2,-3) 14(-1.8,-3) 15(-1.4,-3) 16(-1,-3) 17(-0.6,-3) 18(-0.2,-3) 19(0.2,-3) 20(0.6,-3) 21(1,-3) 22(1.4,-3) 23(1.8,-3) 24(2.2,-3) 37(2.2,3) 38(1.8,3) 39(1.4,3) 40(1,3) 41(0.6,3) 42(0.2,3) 43(-0.2,3) 44(-0.6,3) 45(-1,3) 46(-1.4,3) 47(-1.8,3) 48(-2.2,3)
  rect 3.4x3.4 smd paste-10 mask+0.05: 49(0,0)
  silkscreen extent -3.26,-3.18 3.18,3.29, body extent -3.05,-3.05 3.05,3.05, height 0.9
A1101R09C00GM [mm] "Sub-GHz Modules 900MHz Radio Only Connector"
  oval 1.85x0.55 smd: 1(-4.325,3.5) 2(-4.325,2.5) 3(-4.325,1.5) 4(-4.325,0.5) 5(-4.325,-0.5) 6(-4.325,-1.5) 7(-4.325,-2.5) 8(-4.325,-3.5) 17(4.325,-3.5) 18(4.325,-2.5) 19(4.325,-1.5) 20(4.325,-0.5) 21(4.325,0.5) 22(4.325,1.5) 23(4.325,2.5) 24(4.325,3.5)
  oval 0.55x1.85 smd: 9(-3.5,-5.825) 10(-2.5,-5.825) 11(-1.5,-5.825) 12(-0.5,-5.825) 13(0.5,-5.825) 14(1.5,-5.825) 15(2.5,-5.825) 16(3.5,-5.825)
  rect 1x1 smd: MP1(-4.325,5.5) MP2(4.325,5.5) MP3(-1,2.25) MP4(1,2.25)
  silkscreen extent -5.53,-6.3 5.13,6.86, body extent -4.6,-6.1 4.6,6.1, height 2.1
BGA100 [mm] "BGA, 100-Leads, Body 14.00x18.00mmx1.40mm, Pitch 1.00mm"
  round 0.41 smd: A1(-4.5,8) A2(-3.5,8) A3(-2.5,8) A9(3.5,8) A10(4.5,8) B1(-4.5,7) B2(-3.5,7) B3(-2.5,7) B10(4.5,7) C0(-5.5,6) C2(-3.5,6) C3(-2.5,6) C4(-1.5,6) D0(-5.5,5) D1(-4.5,5) D2(-3.5,5) D3(-2.5,5) D4(-1.5,5) D5(-0.5,5) D6(0.5,5) D7(1.5,5) D8(2.5,5) D9(3.5,5) D10(4.5,5) E1(-4.5,4) E2(-3.5,4) E3(-2.5,4) E4(-1.5,4) E5(-0.5,4) E6(0.5,4) E7(1.5,4) E8(2.5,4) E9(3.5,4) E10(4.5,4) E11(5.5,4) F1(-4.5,3) F2(-3.5,3) F3(-2.5,3) F4(-1.5,3) F5(-0.5,3) F6(0.5,3) F7(1.5,3) F8(2.5,3) F9(3.5,3) F10(4.5,3) F11(5.5,3) G2(-3.5,2) G3(-2.5,2) G4(-1.5,2) G5(-0.5,2) G6(0.5,2) G7(1.5,2) G8(2.5,2) G9(3.5,2) G10(4.5,2) G11(5.5,2) H1(-4.5,1) H2(-3.5,1) H3(-2.5,1) H4(-1.5,1) H5(-0.5,1) H6(0.5,1) H7(1.5,1) H8(2.5,1) H9(3.5,1) H10(4.5,1) H11(5.5,1) J1(-4.5,0) J2(-3.5,0) J3(-2.5,0) J4(-1.5,0) J5(-0.5,0) J6(0.508,0) J7(1.5,0) J8(2.5,0) J9(3.5,0) J10(4.5,0) J11(5.5,0) K1(-4.5,-1) K2(-3.5,-1) K3(-2.5,-1) K4(-1.5,-1) K5(-0.5,-1) K6(0.5,-1) K7(1.5,-1) K8(2.5,-1) K9(3.5,-1) K10(4.5,-1) K11(5.5,-1) L2(-3.5,-2) L3(-2.5,-2) L4(-1.5,-2) L5(-0.5,-2) L6(0.5,-2) L7(1.5,-2) L8(2.5,-2) L9(3.5,-2) L10(4.5,-2) L11(5.5,-2) M2(-3.5,-3) M3(-2.5,-3) M4(-1.5,-3) M5(-0.5,-3) M6(0.5,-3) M7(1.5,-3) M8(2.5,-3) M9(3.5,-3) M11(5.5,-3) N2(-3.5,-4) N3(-2.5,-4) N4(-1.5,-4) N5(-0.5,-4) N6(0.5,-4) N7(1.5,-4) N8(2.5,-4) N9(3.5,-4) N11(5.5,-4) P0(-5.5,-5) P1(-4.5,-5) P2(-3.5,-5) P3(-2.5,-5) P4(-1.5,-5) P5(-0.5,-5) P6(0.5,-5) P7(1.5,-5) P8(2.5,-5) P9(3.5,-5) P11(5.5,-5) R0(-5.5,-6) R1(-4.5,-6) R10(4.5,-6) R11(5.5,-6) T1(-4.5,-7) T10(4.5,-7) U1(-4.5,-8) U2(-3.5,-8) U3(-2.5,-8) U4(-1.5,-8) U5(-0.5,-8) U8(2.5,-8) U9(3.5,-8) U10(4.5,-8)
  silkscreen extent -7.62,-9 7,9.65, body extent -7,-9 7,9, height 1.4
CAP0402 [mm]
  rect 0.51x0.535 smd mask+0.05: 1(-0.42,0) 2(0.42,0)
  silkscreen extent -0.85,-0.45 0.85,0.45, body extent -0.51,-0.25 0.51,0.25, height 0.51
CAP0603 [mm]
  rect 0.75x0.75 smd mask+0.05: 1(-0.72,0) 2(0.72,0)
  silkscreen extent -1.3,-0.55 1.3,0.55, body extent -0.8,-0.4 0.8,0.4, height 0.8
CAP1206 [mm]
  rect 1.15x1.8 smd: 1(-1.5,0) 2(1.5,0)
  silkscreen extent -2.3,-1.17 2.35,1.15, body extent -1.7,-0.9 1.7,0.9, height 0.88
CONN1X03 [mm]
  round 1.4 hole 0.8: 1(-2,0) 2(0,0) 3(2,0)
  round 0.75 hole 0.75 mask-0.5: ""(-2.95,-1.9) ""(2.95,1.9)
  rect 0.9x1.6 smd mask+0.05: ""(-2,-1.9) ""(0,-1.9) ""(2,-1.9) ""(2,1.9)
  rect 0.9x1.6 smd mask+0: ""(-2,1.9) ""(0,1.9)
  silkscreen extent -3.97,-2.55 3.58,2.68, body extent -3.25,-2.4 3.25,2.4, height 5.2
IMX6-SoM [mm]
  rect 0.8x1.5 smd: 1(-17.5,-17.85) 2(-16.5,-17.85) 3(-15.5,-17.85) 4(-14.5,-17.85) 5(-13.5,-17.85) 6(-12.5,-17.85) 7(-11.5,-17.85) 8(-10.5,-17.85) 9(-9.5,-17.85) 10(-8.5,-17.85) 11(-7.5,-17.85) 12(-6.5,-17.85) 13(-5.5,-17.85) 14(-4.5,-17.85) 15(-3.5,-17.85) 16(-2.5,-17.85) 17(-1.5,-17.85) 18(-0.5,-17.85) 19(0.5,-17.85) 20(1.5,-17.85) 21(2.5,-17.85) 22(3.5,-17.85) 23(4.5,-17.85) 24(5.5,-17.85) 25(6.5,-17.85) 26(7.5,-17.85) 27(8.5,-17.85) 28(9.5,-17.85) 29(10.5,-17.85) 30(11.5,-17.85) 31(12.5,-17.85) 32(13.5,-17.85) 33(14.5,-17.85) 34(15.5,-17.85) 35(16.5,-17.85) 36(17.5,-17.85) 71(17.5,17.85) 72(16.5,17.85) 73(15.5,17.85) 74(14.5,17.85) 75(13.5,17.85) 76(12.5,17.85) 77(11.5,17.85) 78(10.5,17.85) 79(9.5,17.85) 80(8.5,17.85) 81(7.5,17.85) 82(6.5,17.85) 83(5.5,17.85) 84(4.5,17.85) 85(3.5,17.85) 86(2.5,17.85) 87(1.5,17.85) 88(0.5,17.85) 89(-0.5,17.85) 90(-1.5,17.85) 91(-2.5,17.85) 92(-3.5,17.85) 93(-4.5,17.85) 94(-5.5,17.85) 95(-6.5,17.85) 96(-7.5,17.85) 97(-8.5,17.85) 98(-9.5,17.85) 99(-10.5,17.85) 100(-11.5,17.85) 101(-12.5,17.85) 102(-13.5,17.85) 103(-14.5,17.85) 104(-15.5,17.85) 105(-16.5,17.85) 106(-17.5,17.85)
  rect 1.5x0.8 smd: 37(18.85,-16.5) 38(18.85,-15.5) 39(18.85,-14.5) 40(18.85,-13.5) 41(18.85,-12.5) 42(18.85,-11.5) 43(18.85,-10.5) 44(18.85,-9.5) 45(18.85,-8.5) 46(18.85,-7.5) 47(18.85,-6.5) 48(18.85,-5.5) 49(18.85,-4.5) 50(18.85,-3.5) 51(18.85,-2.5) 52(18.85,-1.5) 53(18.85,-0.5) 54(18.85,0.5) 55(18.85,1.5) 56(18.85,2.5) 57(18.85,3.5) 58(18.85,4.5) 59(18.85,5.5) 60(18.85,6.5) 61(18.85,7.5) 62(18.85,8.5) 63(18.85,9.5) 64(18.85,10.5) 65(18.85,11.5) 66(18.85,12.5) 67(18.85,13.5) 68(18.85,14.5) 69(18.85,15.5) 70(18.85,16.5) 107(-18.85,16.5) 108(-18.85,15.5) 109(-18.85,14.5) 110(-18.85,13.5) 111(-18.85,12.5) 112(-18.85,11.5) 113(-18.85,10.5) 114(-18.85,9.5) 115(-18.85,8.5) 116(-18.85,7.5) 117(-18.85,6.5) 118(-18.85,5.5) 119(-18.85,4.5) 120(-18.85,3.5) 121(-18.85,2.5) 122(-18.85,1.5) 123(-18.85,0.5) 124(-18.85,-0.5) 125(-18.85,-1.5) 126(-18.85,-2.5) 127(-18.85,-3.5) 128(-18.85,-4.5) 129(-18.85,-5.5) 130(-18.85,-6.5) 131(-18.85,-7.5) 132(-18.85,-8.5) 133(-18.85,-9.5) 134(-18.85,-10.5) 135(-18.85,-11.5) 136(-18.85,-12.5) 137(-18.85,-13.5) 138(-18.85,-14.5) 139(-18.85,-15.5) 140(-18.85,-16.5)
  silkscreen extent -19.87,-18.9 19.6,18.6, body extent -19.5,-18.5 19.5,18.5, height 3
L_1212AB [mm]
  rect 1.75x0.6 smd: 1(-1.55,0) 2(1.55,0)
  silkscreen extent -1.83,-1.5 1.83,1.5, body extent -1.83,-1.45 1.83,1.55, height 2
PGAx13 [mm]
  rect 0.9x0.9 hole 0.6 mask+0.1: A1(0,0)
  round 0.9 hole 0.6 mask+0.1: A2(2.54,0) A3(5.08,0) A4(7.62,0) A5(10.16,0) A6(12.7,0) A7(15.24,0) A8(17.78,0) A9(20.32,0) A10(22.86,0) A11(25.4,0) A12(27.94,0) A13(30.48,0) B1(0,2.54) B2(2.54,2.54) B3(5.08,2.54) B4(7.62,2.54) B5(10.16,2.54) B6(12.7,2.54) B7(15.24,2.54) B8(17.78,2.54) B9(20.32,2.54) B10(22.86,2.54) B11(25.4,2.54) B12(27.94,2.54) B13(30.48,2.54) D1(0,7.62) D2(2.54,7.62) D3(5.08,7.62) D4(7.62,7.62) D5(10.16,7.62) D6(12.7,7.62) D7(15.24,7.62) D8(17.78,7.62) D9(20.32,7.62) D10(22.86,7.62) D11(25.4,7.62) D12(27.94,7.62) D13(30.48,7.62) E1(0,10.16) E2(2.54,10.16) E3(5.08,10.16) E4(7.62,10.16) E5(10.16,10.16) E6(12.7,10.16) E7(15.24,10.16) E8(17.78,10.16) E9(20.32,10.16) E10(22.86,10.16) E11(25.4,10.16) E12(27.94,10.16) E13(30.48,10.16) M1(0,27.94) M2(2.54,27.94) M3(5.08,27.94) M4(7.62,27.94) M5(10.16,27.94) M6(12.7,27.94) M7(15.24,27.94) M8(17.78,27.94) M9(20.32,27.94) M10(22.86,27.94) M11(25.4,27.94) M12(27.94,27.94) M13(30.48,27.94)
  silkscreen extent -4,-1.64 35.02,32.36
QFN64 [mm] "QFN, 64-Leads, Body 9.00x9.00mm, Pitch 0.50mm, Thermal Pad 7.25x7.25mm, IPC Medium Density"
  oval 0.85x0.25 smd mask+0.05: 1(-4.375,3.75) 16(-4.375,-3.75) 33(4.375,-3.75) 48(4.375,3.75)
  oval 0.85x0.25 smd mask+0.07: 2(-4.375,3.25) 3(-4.375,2.75) 4(-4.375,2.25) 5(-4.375,1.75) 6(-4.375,1.25) 7(-4.375,0.75) 8(-4.375,0.25) 9(-4.375,-0.25) 10(-4.375,-0.75) 11(-4.375,-1.25) 12(-4.375,-1.75) 13(-4.375,-2.25) 14(-4.375,-2.75) 15(-4.375,-3.25) 34(4.375,-3.25) 35(4.375,-2.75) 36(4.375,-2.25) 37(4.375,-1.75) 38(4.375,-1.25) 39(4.375,-0.75) 40(4.375,-0.25) 41(4.375,0.25) 42(4.375,0.75) 43(4.375,1.25) 44(4.375,1.75) 45(4.375,2.25) 46(4.375,2.75) 47(4.375,3.25)
  oval 0.25x0.85 smd mask+0.05: 17(-3.75,-4.375) 32(3.75,-4.375) 49(3.75,4.375) 64(-3.75,4.375)
  oval 0.25x0.85 smd mask+0.07: 18(-3.25,-4.375) 19(-2.75,-4.375) 20(-2.25,-4.375) 21(-1.75,-4.375) 22(-1.25,-4.375) 23(-0.75,-4.375) 24(-0.25,-4.375) 25(0.25,-4.375) 26(0.75,-4.375) 27(1.25,-4.375) 28(1.75,-4.375) 29(2.25,-4.375) 30(2.75,-4.375) 31(3.25,-4.375) 50(3.25,4.375) 51(2.75,4.375) 52(2.25,4.375) 53(1.75,4.375) 54(1.25,4.375) 55(0.75,4.375) 56(0.25,4.375) 57(-0.25,4.375) 58(-0.75,4.375) 59(-1.25,4.375) 60(-1.75,4.375) 61(-2.25,4.375) 62(-2.75,4.375) 63(-3.25,4.375)
  rect 7.25x7.25 smd paste+0 mask+0.07: ""(-0.001,-0.007)
  silkscreen extent -5.5,-4.72 4.72,4.72, body extent -4.57,-4.57 4.57,4.57, height 0.8
RES0402 [mm]
  rect 0.51x0.54 smd mask+0.05: 1(-0.41,0) 2(0.41,0)
  silkscreen extent -0.85,-0.45 0.85,0.45, body extent -0.5,-0.25 0.5,0.25, height 0.35
TestPoint_2019 [mm]
  round 0.5 smd paste-10 mask+0.1: 1(0,0)

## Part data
C1001 C1002 C1003 C1004 C1101 C1102 C1103 C1104 C2002 C2003 C2004 C2102 C2103 C2104 C3001 C3002 C3004 C3005 C3006 C3007 C4009 C5002 C5003 C5004 C5005 C5006 C6001 C6002 C6003: library part C0402_100nF, "CAP CER 100nF SMD 0402", Manufacturer=Murata, Manufacturer Part Number=GJM1555C1H100JB01D
C1005 C1105 C2001 C2101 C3000 C4001 C4002 C5001: library part C0603_10uF, "CAP CER 10uF  SMD 0603", Manufacturer=Murata, Manufacturer Part Number=GJM1555C1H100JB01D
C3003: library part C0402_10nF, "CAP CER 10nF SMD 0402", Manufacturer=Murata, Manufacturer Part Number=GJM1555C1H100JB01D
C4003 C4004 C4005 C4006 C4007 C4008 C4019: library part C0603_2.2uF, "CAP CER 2.2uF  SMD 0603", Manufacturer=Murata, Manufacturer Part Number=GJM1555C1H100JB01D
C4010 C4012: library part C0402_4.7uF, "CAP CER 4.7upF SMD 0402", Manufacturer=Murata, Manufacturer Part Number=GJM1555C1H100JB01D
C4011 C4013 C4015 C4017: library part C1206_47uF, "CAP CER 47uF  SMD 1206", Manufacturer=Murata, Manufacturer Part Number=GJM1555C1H100JB01D
C4014 C4016: library part C0603_4.7uF, "CAP CER 4.7uF  SMD 0603", Manufacturer=Murata, Manufacturer Part Number=GJM1555C1H100JB01D
IC1000: library part 1IMG219
IC3000: "528MHz NXP i.MX 6UL/6ULL ARM Cortex-A7 Processors"
IC5000: "BGA100"
IC6000: "MOD26"
L4000 L4002 L4003 L4004: library part IHLP1212AB
R4001: library part R0402_4.7k, "RES TKF 4.7k SMD 0402", Manufacturer="TE Connectivity", Manufacturer Part Number=CRG0402F10K, Tolerance=1%
R4002 R4003 R4006 R4007 R4008 R4009: library part R0402_0R, "RES TKF 0R  SMD 0402", Manufacturer="TE Connectivity", Manufacturer Part Number=CRG0402F10K, Tolerance=1%
R4004: library part R0402_49.9R, "RES TKF 49.9R SMD 0402", Manufacturer="TE Connectivity", Manufacturer Part Number=CRG0402F10K, Tolerance=1%
R4005: library part R0402_10k, "RES TKF 10k  SMD 0402", Manufacturer="TE Connectivity", Manufacturer Part Number=CRG0402F10K, Tolerance=1%
TH4000: library part Thermistor, "THERMISTOR 10K OHM  0402"
TP3000 TP3001 TP3002 TP3003 TP3004 TP3005 TP3006 TP3007 TP3008 TP4010 TP4011 TP_CLK TP_CMD TP_D0 TP_D1 TP_D2 TP_D3 TP_D4 TP_D5 TP_D6 TP_D7 TP_DS TP_RST: "SMD test point", Manufacturer=NA

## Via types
v1: diameter 0.4, hole 0.2, Signal 1 to Signal 8, 276 vias
v2: diameter 0.6, hole 0.3, Signal 1 to Signal 8, 49 vias
v3: diameter 0.325, hole 0.125, Signal 1 to GND/Signal 2, 9 vias
v4: diameter 0.5, hole 0.2, GND/Signal 2 to GND 7, 9 vias
v5: diameter 0.4, hole 0.2, Signal 1 to Signal 8, tented both sides, 9 vias

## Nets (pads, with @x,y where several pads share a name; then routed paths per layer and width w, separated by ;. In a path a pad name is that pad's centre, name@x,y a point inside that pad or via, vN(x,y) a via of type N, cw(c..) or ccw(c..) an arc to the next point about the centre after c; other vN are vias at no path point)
+V_IN: C4001.2 C4002.2 C4003.2 C4004.1 C4005.1 C4009.2 C4010.1 C4012.1 C4014.1 C4016.1 CN40000.2 IC4000.8 IC4000.10 IC4000.18 IC4000.22 IC4000.29 IC4000.32 IC4000.34 IC4000.37 IC4000.42 IC4000.46 R4001.2 | length 27.8
  Signal 1 w0.1: C4009.2@91.22,21.5 91.62,21.5 92,21.88 v1(92,21.9) 92.45,22.35 IC4000.34@93.175,22.35 93.65,22.35 93.8,22.5 93.8,23 93.65,23.15 IC4000.32@93.175,23.15 ; C4010.1@91.6,25.3 92.1,24.8 v1(92.25,24.8) 92.3,24.8 92.75,24.35 IC4000.29@93.175,24.35 ; C4012.1@91.7,23.8 v1(92.2,23.8) ; v1(91.9,20.7) 92.115,20.485 C4002.2@92.115,19.65 ; v1(93.3,20) 93.3,20.075 IC4000.37@93.975,20.75 ; IC4000.22@94.775,26.75 94.775,26.125 94.9,26 96.2,26 96.375,26.175 IC4000.18@96.375,26.75 v1(96.375,27.702) 96.375,28.655 C4016.1@96.4,28.68 C4003.2@95.1,28.68 ; IC4000.42@95.975,20.75 95.975,21.375 96.1,21.5 97.5,21.5 97.575,21.425 IC4000.46@97.575,20.75 97.575,20.252 v1(98.109,19.719) 98.88,18.947 C4005.1@98.88,18.5 v1@98,18.5 ; v1(97.9,17.1) C4001.2@98.86,17.1 98.86,16.14 v1@98.84,16.14 ; IC4000.8@99.175,24.35 99.49,24.35 C4004.1@100.5,23.34 ; IC4000.10@99.175,25.15 99.95,25.15 v1(100,25.1) ; v1(100.1,26.4) C4014.1@100.88,26.4 ; R4001.2@102.525,28.96 v1@102.525,29.85
  other v1: 98.869,16.159 98.009,18.519 100.004,23.864 102.534,29.869
+V_LDO_RF_3V3: C4019.2 IC4000.23 | length 1.9
  Signal 1 w0.1: C4019.2@93.5,27.9 94.1,27.9 94.4,27.6 94.4,26.775 IC4000.23@94.375,26.75
+V_SMPS_1V8: C1101.2 C1102.2 C1103.2 C1104.2 C1105.2 C2101.2 C2102.2 C2103.2 C2104.2 C4011.2 C4013.2 IC1000.A1 IC1000.A2 IC1000.A3 IC1000.A4 IC1000.A5 IC1000.A6 IC1000.A7 IC1000.D7 IC1000.D9 IC1000.D11 IC1000.D13 IC2000.35 L4000.2 L4002.2 R4006.2 R4007.2 TP3006.1 | length 286
  Signal 1 w0.1: C4011.2@85.675,17.05 85.725,17.1 L4000.2@85.725,20.05 ; v1(89.824,26.805) 89.829,26.8 90.38,26.8 R4007.2@90.795,26.385 ; R4007.2@90.795,26.4 88.475,26.4 88.475,27.025 87.3,28.2 84.8,28.2 83.8,27.2 83.8,21.975 L4000.2@85.725,20.05 ; R4006.2@90.875,22.65 88.975,22.65 C4013.2@88.575,23.05 85.725,20.2 L4000.2@85.725,20.05 ; v1(107.324,76.005) 107.324,77.131 107.28,77.175 107.28,77.677 108.061,78.457 108.061,79.656 108.08,79.675 108.06,79.695 C2104.2@108.06,80.675 ; C2104.2@108.08,80.6 108.12,80.64 108.1,80.66 v1(108.1,81.3) ; IC2000.35@109.274,91.04 109.274,92.206 v1(109.576,92.507) ; C1104.2@241.1,78.32 v1@241.1,79.1 ; 243.5,78.6 v1(243.5,79.125) ; C1102.2@246.3,78.32 v1@246.3,79 ; C1101.2@248.6,78.32 v1@248.6,79.1 ; v1@251.118,79.282 C1105.2@251.118,78.375 251.168,78.425 v1(252.2,78.425) 253.3,77.325 TP3006.1@253.3,69.7
  Signal 4 w0.1: v1(89.824,26.805) 89.824,31.676 91.9,33.752 91.9,45.6 107.3,61 v1@107.3,76
  Power/Signal 6 w0.1: v1(109.576,92.507) 109.576,91.769 109.074,91.267 109.074,85.479 109.074,82.274 v1(108.1,81.3) 108.5,80.9 144.3,80.9 150.8,74.4 192.3,74.4 194.5,76.6 210.7,76.6 215.4,71.9 233.6,71.9 235.76,74.06 IC1000.A7@235.76,81.24 235.76,82.04 234.7,83.1 234.7,85.3 235.76,86.36 IC1000.D7@235.76,88.56 ; IC1000.D13@220.52,88.86 220.52,87.98 220.94,87.56 224.3,87.56 IC1000.D11@225.6,88.86 225.6,88.2 226.1,87.7 229.52,87.7 IC1000.D9@230.68,88.86 232.04,87.5 234.7,87.5 IC1000.D7@235.76,88.56 ; IC1000.D7@235.76,88.86 IC1000.D7@235.76,88.56
  other v1: 246.3,79.025 241.1,79.125 248.6,79.125 251.098,79.308
+V_SMPS_3V3: C1001.2 C1002.2 C1003.2 C1004.2 C1005.2 C2001.2 C2002.2 C2003.2 C2004.2 C3000.1 C3001.1 C3002.1 C3003.1 C3004.1 C3005.1 C3006.1 C3007.1 C4015.2 C4017.2 C5001.1 C5002.1 C5003.1 C5004.2 C5005.2 C5006.2 IC1000.A8 IC1000.A9 IC1000.A10 IC1000.A11 IC1000.A12 IC1000.A13 IC2000.50 IC2000.57 IC2000.60 IC3000.7 IC3000.9 IC3000.11 IC3000.13 IC3000.15 IC3000.37 IC3000.38 IC3000.39 IC3000.109 IC3000.110 IC3000.111 IC3000.112 IC5000.E4 IC5000.F2 IC5000.F3 IC5000.F4 IC5000.F5 IC5000.F6 IC5000.F7 IC5000.F8 IC5000.F9 IC5000.H3 IC5000.H8 IC5000.L2 IC5000.L4 IC5000.L7 IC5000.L9 IC5000.P3 IC5000.P8 L4003.2 L4004.2 R4008.2 R4009.2 TP3008.1 | length 356.6
  Signal 1 w0.07: IC2000.60@102.149,84.915 100.96,84.915 100.4,85.475 100.4,86 100.815,86.415 100.78,86.45 ; IC2000.57@102.149,86.415 101.429,86.415 101.394,86.45 100.78,86.45 ; IC2000.50@102.149,89.915 101.215,89.915 v1(100.4,89.1) 100.4,86.831 100.78,86.45
  Signal 1 w0.09: IC5000.P3@141.7,95.35 141.725,95.35 142.175,95.8 v1(142.2,95.8) ; v1(145.7,103.35) IC5000.F8@146.7,103.35 IC5000.F9@147.7,103.35 ; v1(146.2,95.9) 146.2,95.875 146.7,95.375 IC5000.P8@146.7,95.35 ; IC5000.L9@147.7,98.35 v1(148.2,97.85)
  Signal 1 w0.1: C4017.2@88.6,32.9 91.15,32.9 L4004.2@91.35,32.7 92.15,33.5 v1(95.6,33.5) 97.6,31.5 R4009.2@97.6,30.51 102.89,30.51 103.225,30.175 103.225,27.5 C4015.2@104.875,25.85 ; R4008.2@101.605,24.75 101.955,25.1 ; L4003.2@105.65,23 105.65,25.075 C4015.2@104.875,25.85 ; v1(142.225,98.825) IC5000.L4@142.7,98.35 ; IC3000.109@157.125,77.3 157.125,75.575 C3000.1@158,74.7 ; IC3000.110@158.125,77.3 158.025,77.2 C3000.1@158.025,74.425 ; IC3000.111@159.125,77.3 159.125,75.525 159.1,75.5 ; IC3000.112@160.125,77.3 160.125,76.325 159.3,75.5 159.1,75.5 ; IC3000.39@186.125,115 186.125,116.025 186.7,116.6 187.8,116.6 ; IC3000.38@187.125,115 187.125,115.925 187.8,116.6 ; IC3000.37@188.125,115 188.125,116.125 188.6,116.6 ; IC3000.7@189.475,84.65 v1(192.6,84.65) ; IC3000.9@189.475,86.65 191.65,86.65 192.6,85.7 ; IC3000.11@189.475,88.65 191.85,88.65 192.6,87.9 ; IC3000.13@189.475,90.65 191.65,90.65 192.6,89.7 ; IC3000.15@189.475,92.65 191.95,92.65 192.6,92 ; v1(219.48,77.72) C1005.2@220.5,77.72 220.475,77.745 v1(220.475,78.625) v1@220.475,78.7 ; C1004.2@223,77.62 v1(223,78.55) ; C1003.2@225.6,77.72 v1(225.6,78.5) ; C1002.2@228.2,77.72 v1@228.2,78.525 ; v1(230.775,78.7) 230.8,78.675 C1001.2@230.8,77.9 230.875,77.975 v1@231.675,77.975 ; v1(231.675,78) 231.9,78 233.1,76.8 TP3008.1@233.1,69.7 ; 101.955,25.1 104.125,25.1 C4015.2@104.875,25.85 ; 101.955,25.1 101.955,25.16 101.895,25.1 101.955,25.1 ; C3000.1@158,74.4 158.025,74.375 C3000.1@158.025,74.4 ; C3000.1@158,74.4 C3000.1@158.025,74.425 ; C3000.1@158,74.4 C3000.1@158.025,74.4 ; C3000.1@158.025,74.4 159.88,74.4 C3001.1@159.9,74.42 C3002.1@161.9,74.42 C3003.1@163.9,74.42 C3004.1@165.9,74.42 C3005.1@167.9,74.42 C3006.1@169.9,74.42 C3007.1@171.9,74.42 188.82,74.42 192.6,78.2 v1(192.6,84.65) ; C3000.1@158.025,74.4 C3000.1@158.025,74.425 ; C3000.1@158.025,74.425 159.1,75.5 ; 187.8,116.6 188.6,116.6 ; 188.6,116.6 192.4,116.6 193.1,115.9 193.1,92.5 192.6,92 ; v1(192.6,84.65) 192.6,85.7 ; 192.6,85.7 192.6,87.9 ; 192.6,87.9 192.6,89.7 ; 192.6,89.7 192.6,92
  Power/Signal 6 w0.07: v1(100.4,89.1) 102.3,91 107.935,91 108.915,91.98 108.915,92.108 109.018,92.21 109.018,92.423 110.295,93.7 134.5,93.7 140.2,93.7 142.2,95.7 v1(142.2,95.8)
  Power/Signal 6 w0.09: v1(148.2,97.85) 149.6,96.45 149.6,82.3 154,77.9 154,76.4 155.1,75.3 157.992,75.3 v1(158.027,75.335)
  Power/Signal 6 w0.1: v1(95.6,33.5) 95.6,48.6 102.034,55.034 102.034,83.866 v1(100.4,85.5) ; v1(192.6,84.65) 212.675,84.65 216.085,81.24 IC1000.A13@220.52,81.24
  Signal 8 w0.07: v1(145.727,98.335) 146.213,97.85 v1(148.2,97.85)
  Signal 8 w0.09: 141.827,102.911 141.7,102.784 v1(141.7,101.35) 142.225,100.825 v1(142.225,98.825) 141.75,98.35 v1(140.7,98.35) 140.7,97.225 142.125,95.8 v1(142.2,95.8) 146.175,95.8 146.2,95.775 v1(146.2,95.9) 146.275,95.825 147.975,95.825 148.2,96.05 v1(148.2,97.85) 148.2,99.85 v1(146.7,101.35)
  Signal 8 w0.1: v1(140.7,103.35) v1(141.7,103.35)
  other v1: 228.225,78.55 142.7,103.35 143.7,103.35 144.7,103.35 142.7,104.35
ADC_CLK_N: IC1000.D2 IC2000.59 IC3000.33 | length 189.8
  Signal 1 w0.09: v1(101.1,85.4) 101.32,85.62 101.474,85.62 101.679,85.415 IC2000.59@102.149,85.415 ; IC3000.33@189.475,110.65 190.27,110.65 190.644,111.024 v1(192.724,111.024) ; v1(244.2,90.1) 247.22,90.1 IC1000.D2@248.46,88.86
  Signal 4 w0.09: v1(101.1,85.4) 100.61,85.89 100.61,88.579 101.91,89.879 101.91,94.179 114.321,106.59 116.9,106.59 119.41,109.1 188.5,109.1 190.556,111.156 191.456,111.156 191.924,111.624 191.924,111.657 v1(191.9,111.681) ; v1(192.724,111.024) 192.8,111.1 194.5,111.1 203.5,111.1 243.405,111.1 244.6,109.905 244.6,90.5 v1(244.2,90.1)
  Signal 8 w0.09: v1(191.9,111.681) 191.9,111.6 192.6,110.9 v1(192.724,111.024)
ADC_CLK_P: IC1000.D3 IC2000.58 IC3000.34 | length 185.6
  Signal 1 w0.09: v1(101.1,86) 101.29,85.81 101.574,85.81 101.679,85.915 IC2000.58@102.149,85.915 ; IC3000.34@189.475,111.65 190.27,111.65 190.625,111.295 192.002,111.295 192.307,111.6 v1(192.7,111.6)
  Signal 4 w0.09: v1(101.1,86) 100.8,86.3 100.8,88.5 102.1,89.8 102.1,94.1 114.4,106.4 116.979,106.4 119.489,108.91 188.579,108.91 190.634,110.966 192.166,110.966 192.676,111.476 v1@192.7,111.5 ; v1(192.7,111.6) v1@192.7,111.5 ; IC1000.D3@245.92,88.86 244.79,89.99 244.79,109.984 243.274,111.5 203.5,111.5 194.5,111.5 v1@192.7,111.5
ADC_RESET: IC2000.64 IC3000.41 | length 109.8
  Signal 1 w0.1: v1(101.4,82.4) 101.915,82.915 IC2000.64@102.149,82.915 ; IC3000.41@184.125,115 184.224,115.099 v1(184.224,116.605)
  GND/Signal 2 w0.1: v4(184.181,99.13) 184.181,116.581 v1@184.2,116.6
  Signal 4 w0.1: v1(101.4,82.4) 103.2,84.2 111,84.2 125.975,99.175 144.625,99.175 144.7,99.1 v4@184.1,99.1
BIT_CLK_N: IC2000.26 IC3000.108 | length 54.5
  Signal 1 w0.2: IC2000.26@110.899,87.415 110.934,87.38 122.328,87.38 122.397,87.45 122.675,87.45 v1(122.675,87.417) ; v1(136.675,87.253) 136.895,87.033 136.895,86.997 143.497,80.395 149.31,80.395 149.38,80.325 149.6,80.325 v1(149.6,80.355) ; v1(155.905,75.8) 155.905,77.08 IC3000.108@156.125,77.3
  Signal 4 w0.09: v1(122.675,87.417) 122.697,87.395 122.814,87.395 122.955,87.253 v1(136.675,87.253) ; v1(149.6,80.355) 151.13,78.825 151.13,75.255 151.53,74.855 155.132,74.855 155.783,75.506 155.88,75.603 155.88,75.8 v1(155.905,75.8)
BIT_CLK_P: IC2000.25 IC3000.107 | length 54.5
  Signal 1 w0.2: IC2000.25@110.899,86.915 110.934,86.95 122.325,86.95 122.455,86.82 122.617,86.82 v1(122.617,86.92) ; v1(137.325,87.175) 143.675,80.825 149.25,80.825 149.38,80.955 149.6,80.955 v1(149.6,80.855) ; IC3000.107@155.125,77.3 155.405,77.02 v1(155.405,75.8)
  Signal 4 w0.09: v1(122.617,86.92) 122.638,86.942 122.814,86.942 122.823,86.933 136.323,86.933 136.478,86.778 136.872,86.778 137.15,87.057 137.15,87.175 v1(137.325,87.175) ; v1(149.6,80.855) 149.625,80.83 149.797,80.83 150.075,80.552 150.075,80.38 151.45,79.005 151.45,75.575 151.85,75.175 154.999,75.175 155.437,75.613 155.25,75.8 v1(155.405,75.8)
eMMC_CLK: IC3000.74 IC5000.P6 TP_CMD.1 | length 24.7
  Signal 1 w0.09: v3(144.2,95.8) 144.65,95.35 IC5000.P6@144.7,95.35 ; v1@152.4,110.5 152.55,110.65 IC3000.74@153.775,110.65
  GND/Signal 2 w0.09: v3(144.2,95.8) 142.7,97.3 142.7,99.6 151.5,108.4 151.5,109.59 v1(152.4,110.49)
  Signal 8 w0.09: v1(152.4,110.49) 155.448,110.49 TP_CMD.1@155.6,110.642
eMMC_CMD: IC3000.72 IC5000.P5 TP_CLK.1 | length 38.1
  Signal 1 w0.09: IC5000.P5@143.7,95.35 143.175,94.825 140.5,94.825 140.125,95.2 140.125,96.175 139.05,97.25 139.05,108.025 139.35,108.325 139.35,108.495 143.505,112.65 IC3000.72@153.775,112.65
  Signal 8 w0.09: v1(151.486,112.649) TP_CLK.1@155.677,112.649
eMMC_DATA0: IC3000.78 IC5000.K2 TP_D0.1 | length 23.7
  Signal 1 w0.09: IC5000.K2@140.7,99.35 140.55,99.35 140.175,99.725 140.175,105.45 140.575,105.85 149.625,105.85 150.425,106.65 IC3000.78@153.775,106.65
  Signal 8 w0.09: v1(152.4,106.629) 155.499,106.629 TP_D0.1@155.55,106.578
eMMC_DATA1: IC3000.79 IC5000.N2 TP_D1.1 | length 26.7
  Signal 1 w0.09: IC5000.N2@140.7,96.35 141.3,96.95 141.3,104.6 141.55,104.85 150.35,104.85 v1(150.6,105.1) 150.6,105.175 151.075,105.65 IC3000.79@153.775,105.65
  Signal 8 w0.09: v1(150.6,105.1) 153.1,105.1 153.7,105.7 155.514,105.7 TP_D1.1@155.575,105.639
eMMC_DATA2: IC3000.80 IC5000.K3 TP_D2.1 | length 21.3
  Signal 1 w0.09: IC5000.K3@141.7,99.35 142.225,99.875 142.225,103.575 142.575,103.925 150.825,103.925 v1(151.1,104.2) 151.1,104.275 151.475,104.65 IC3000.80@153.775,104.65
  Signal 8 w0.09: v1@151.1,104.1 151.292,104.292 155.194,104.292 TP_D2.1@155.626,104.724
eMMC_DATA3: IC3000.81 IC5000.N3 TP_D3.1 | length 21.8
  Signal 1 w0.09: IC5000.N3@141.7,96.35 142.2,96.85 144.8,96.85 145.175,97.225 145.175,102.45 145.575,102.85 151.85,102.85 152.222,103.222 v1(152.222,103.251) 152.621,103.65 IC3000.81@153.775,103.65
  Signal 8 w0.09: v1(152.222,103.251) 155.372,103.251 TP_D3.1@155.677,103.556
eMMC_DATA4: IC3000.82 IC5000.N8 TP_D4.1 | length 17.4
  Signal 1 w0.09: IC5000.N8@146.7,96.35 146.2,96.85 146.2,101.5 146.6,101.9 151.525,101.9 152.275,102.65 IC3000.82@153.775,102.65
  Signal 8 w0.09: v1(151.968,102.337) 155.727,102.337 TP_D4.1@155.88,102.489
